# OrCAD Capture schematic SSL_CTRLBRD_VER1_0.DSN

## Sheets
1 3: MOTOR_1: size A3
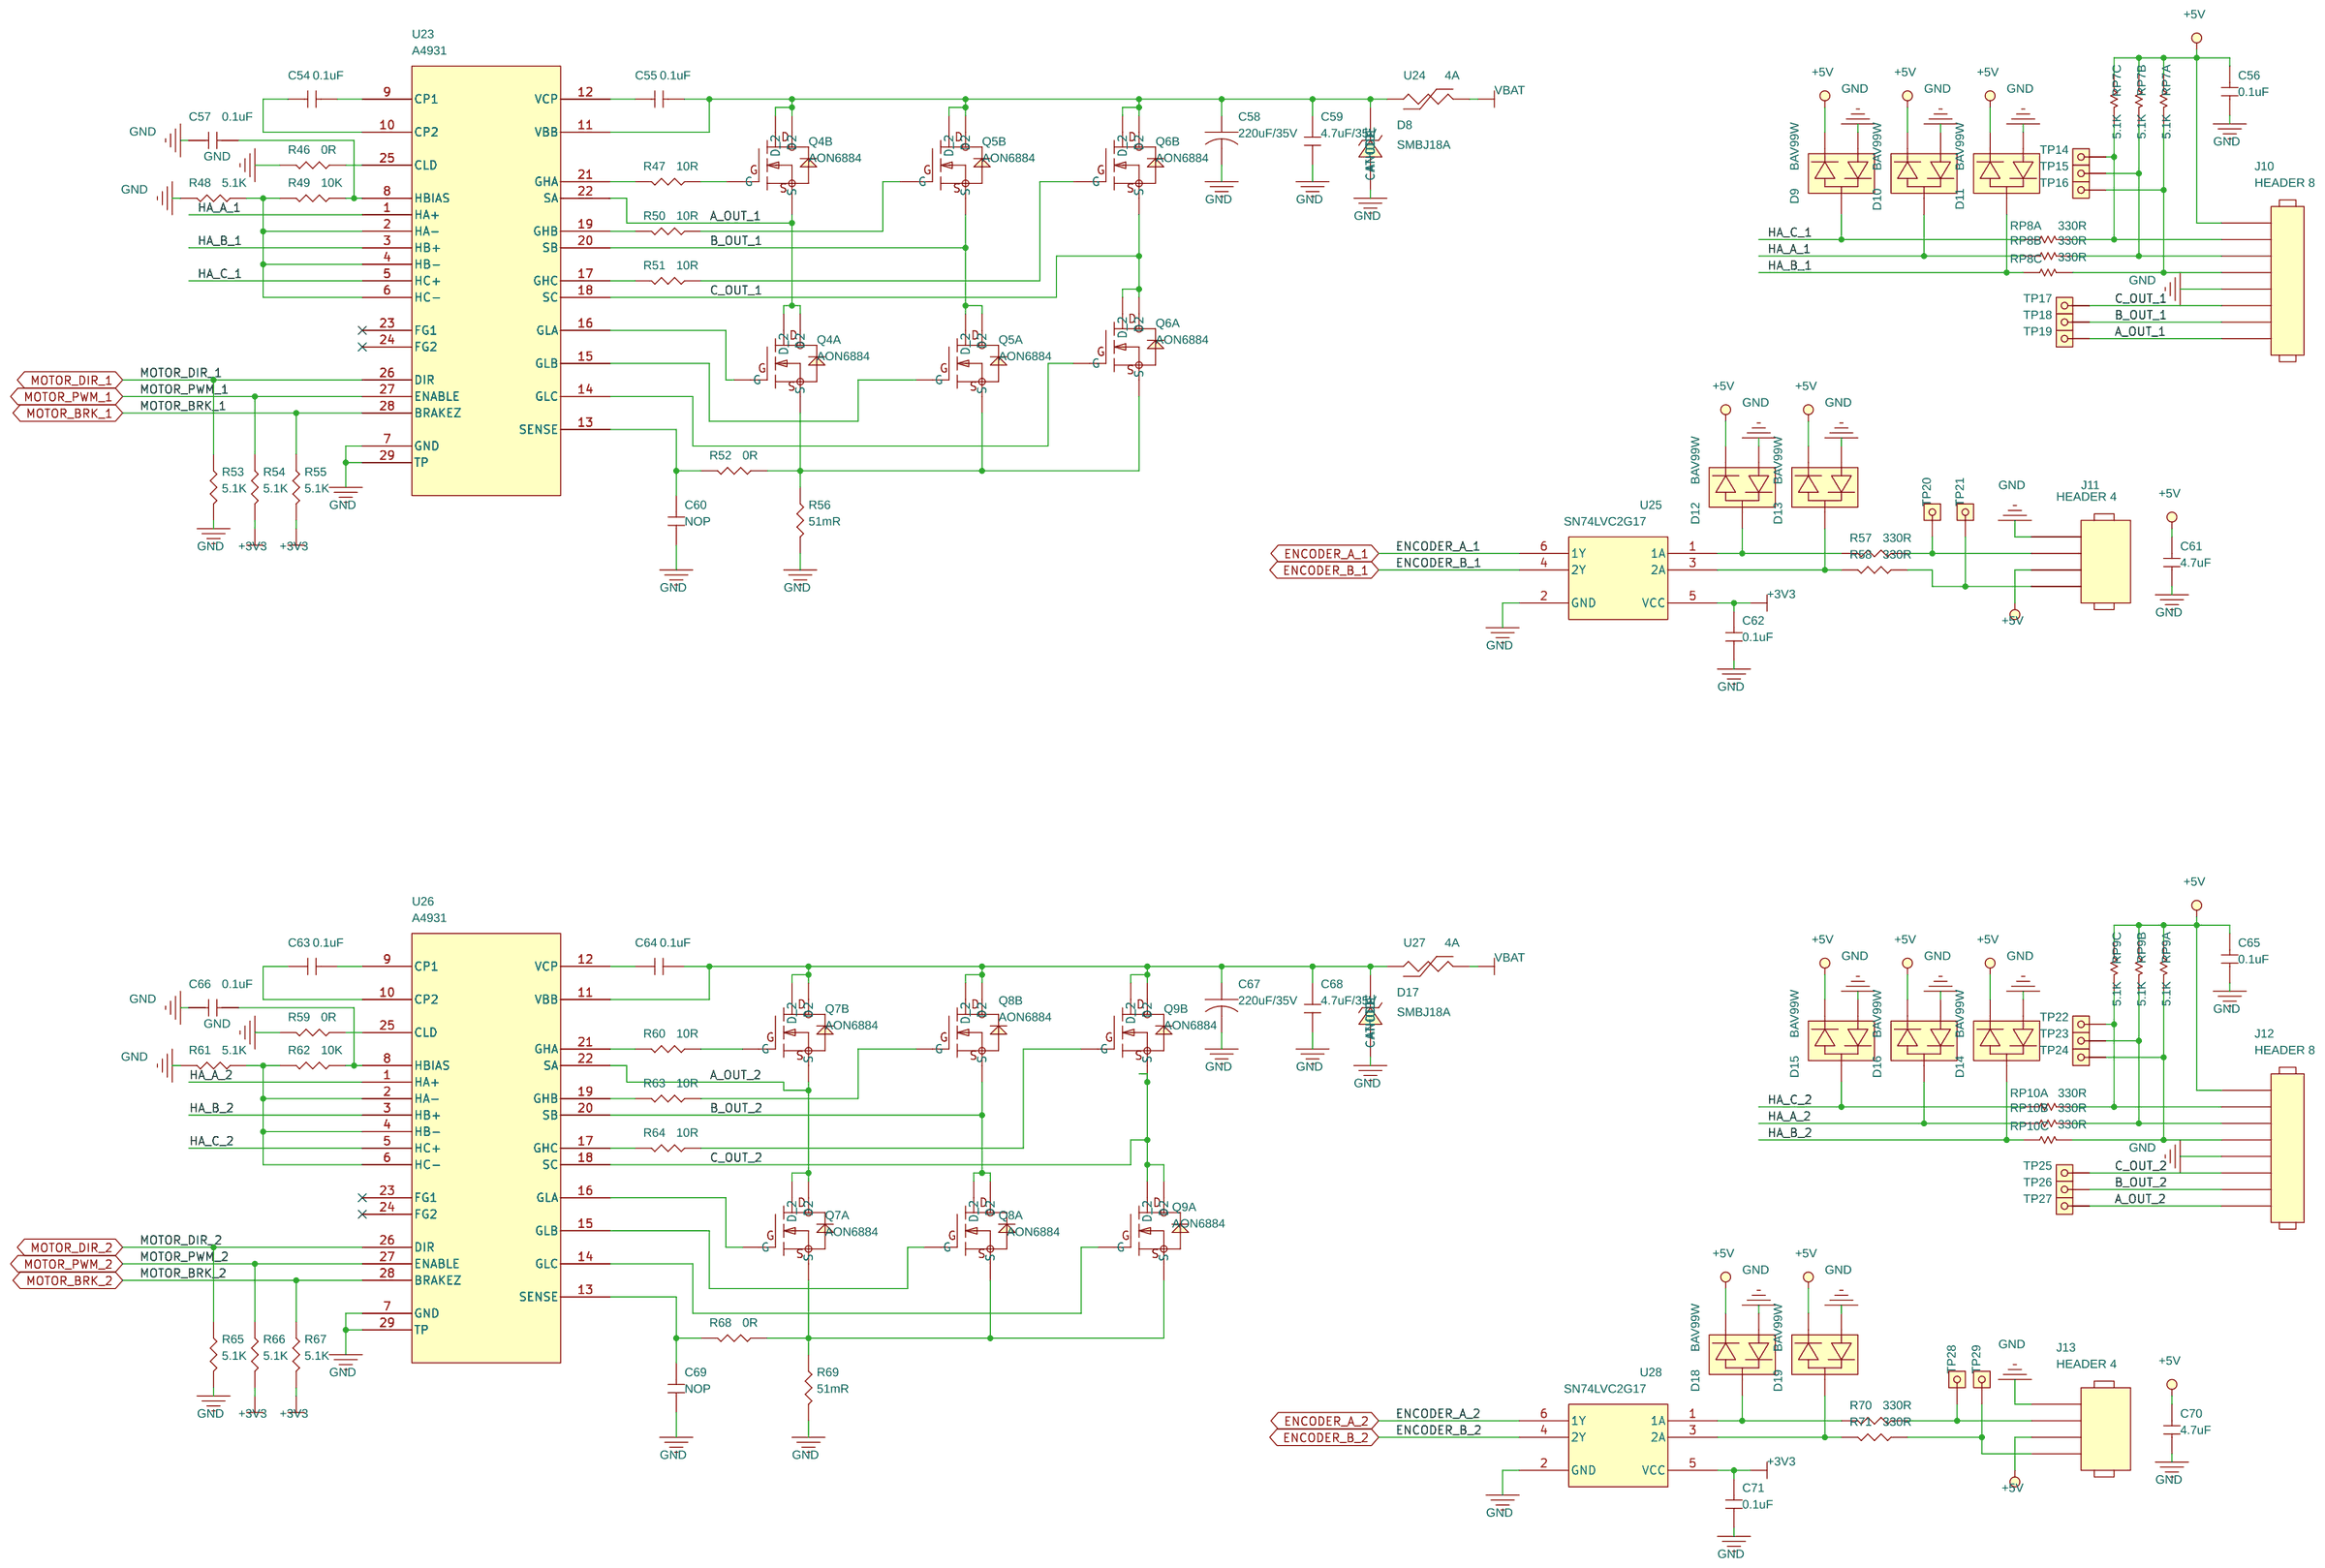
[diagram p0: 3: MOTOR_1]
2 1: MCU: size A3
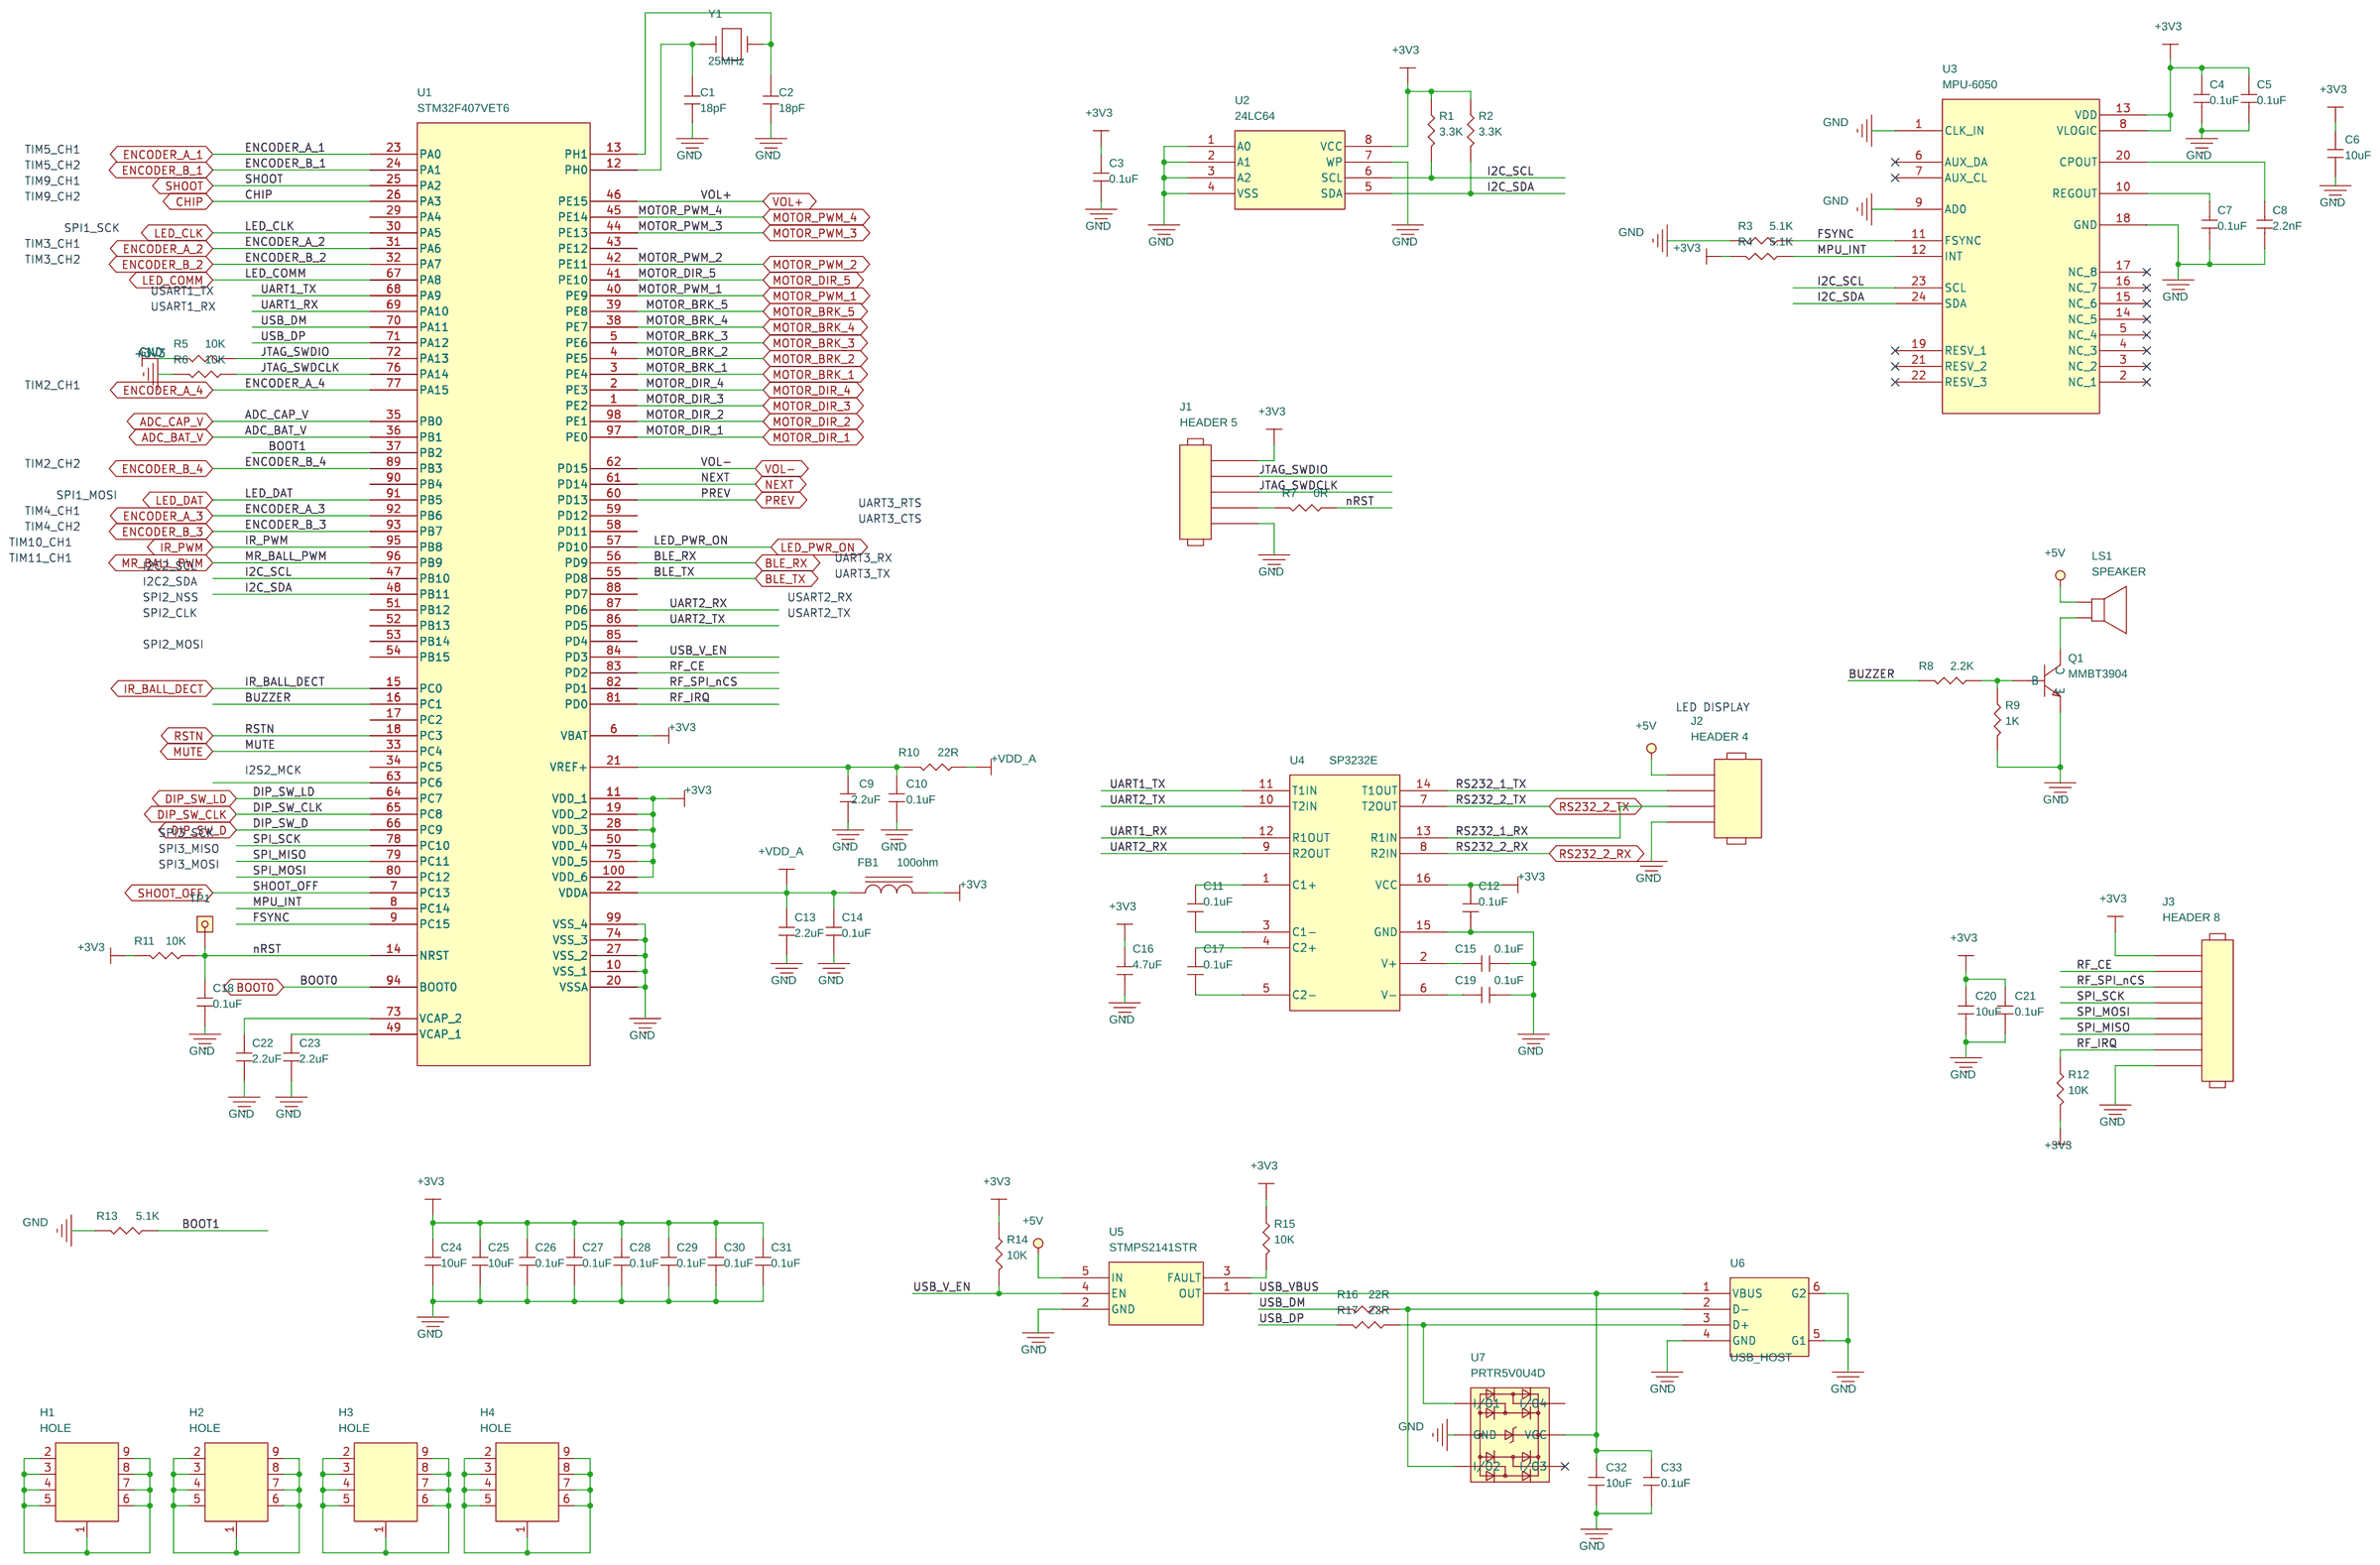
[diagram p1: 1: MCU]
3 2: IO & Power: size A3
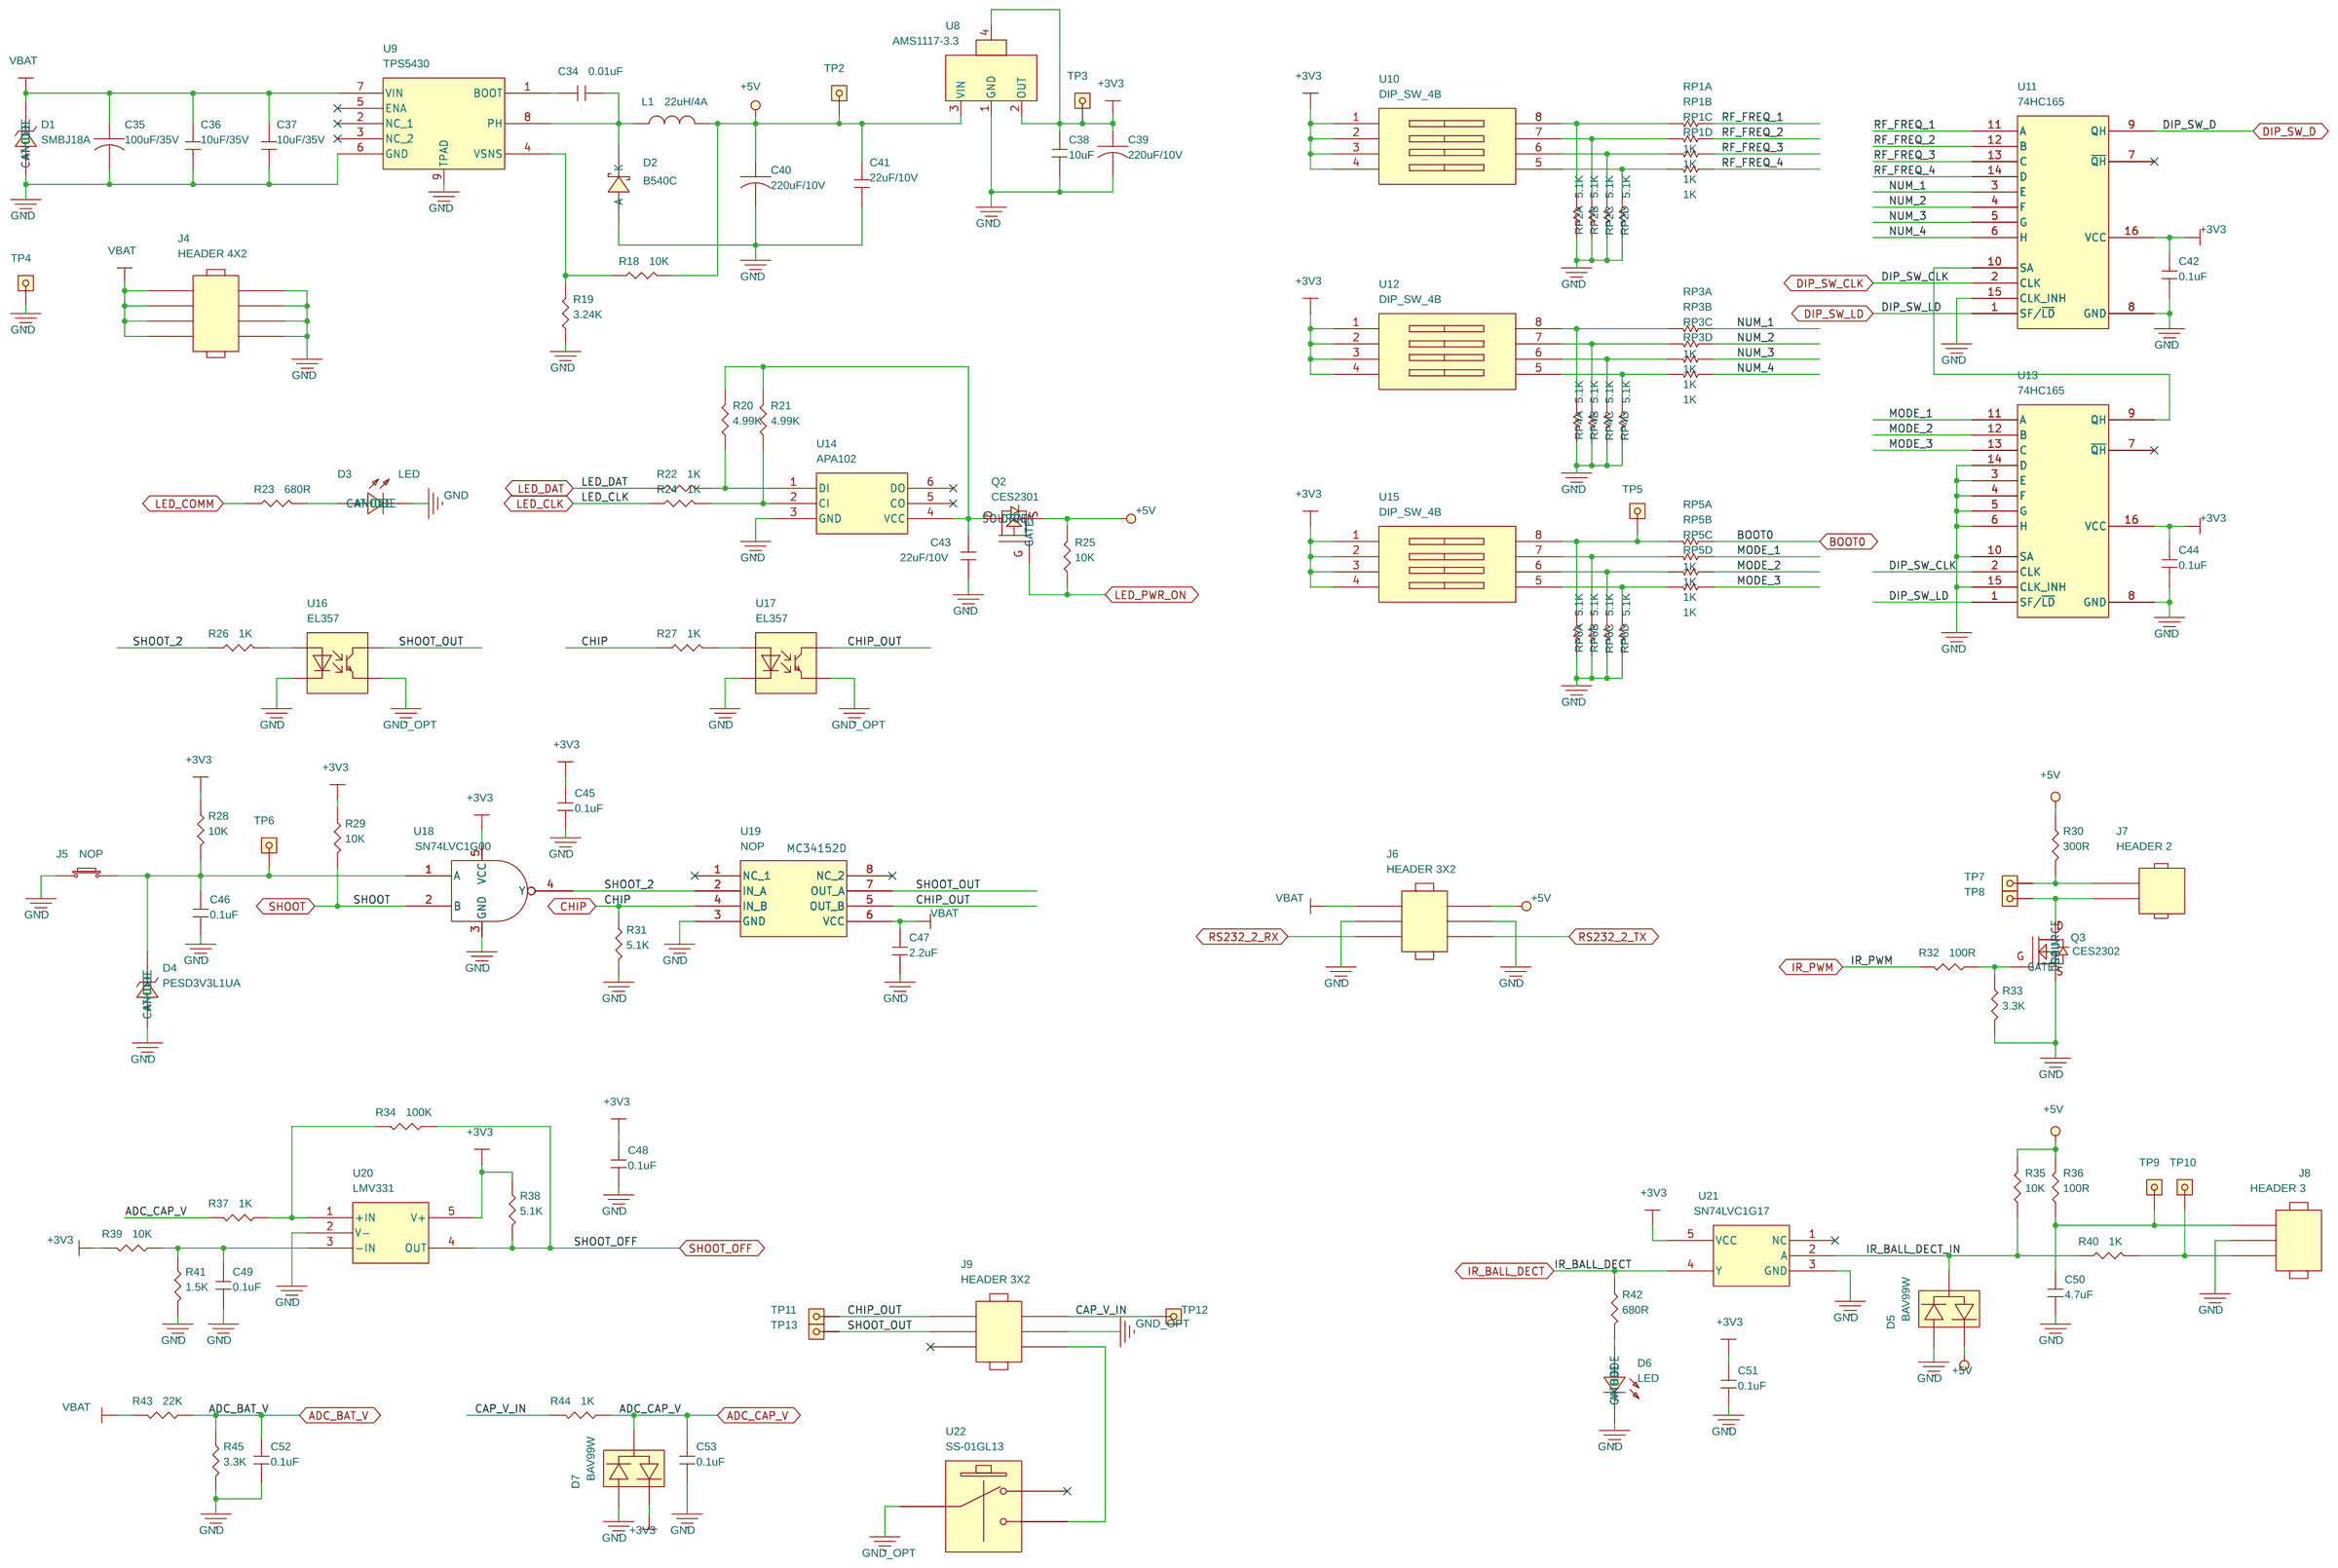
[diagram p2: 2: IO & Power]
4 4: MOTOR_2: size A3
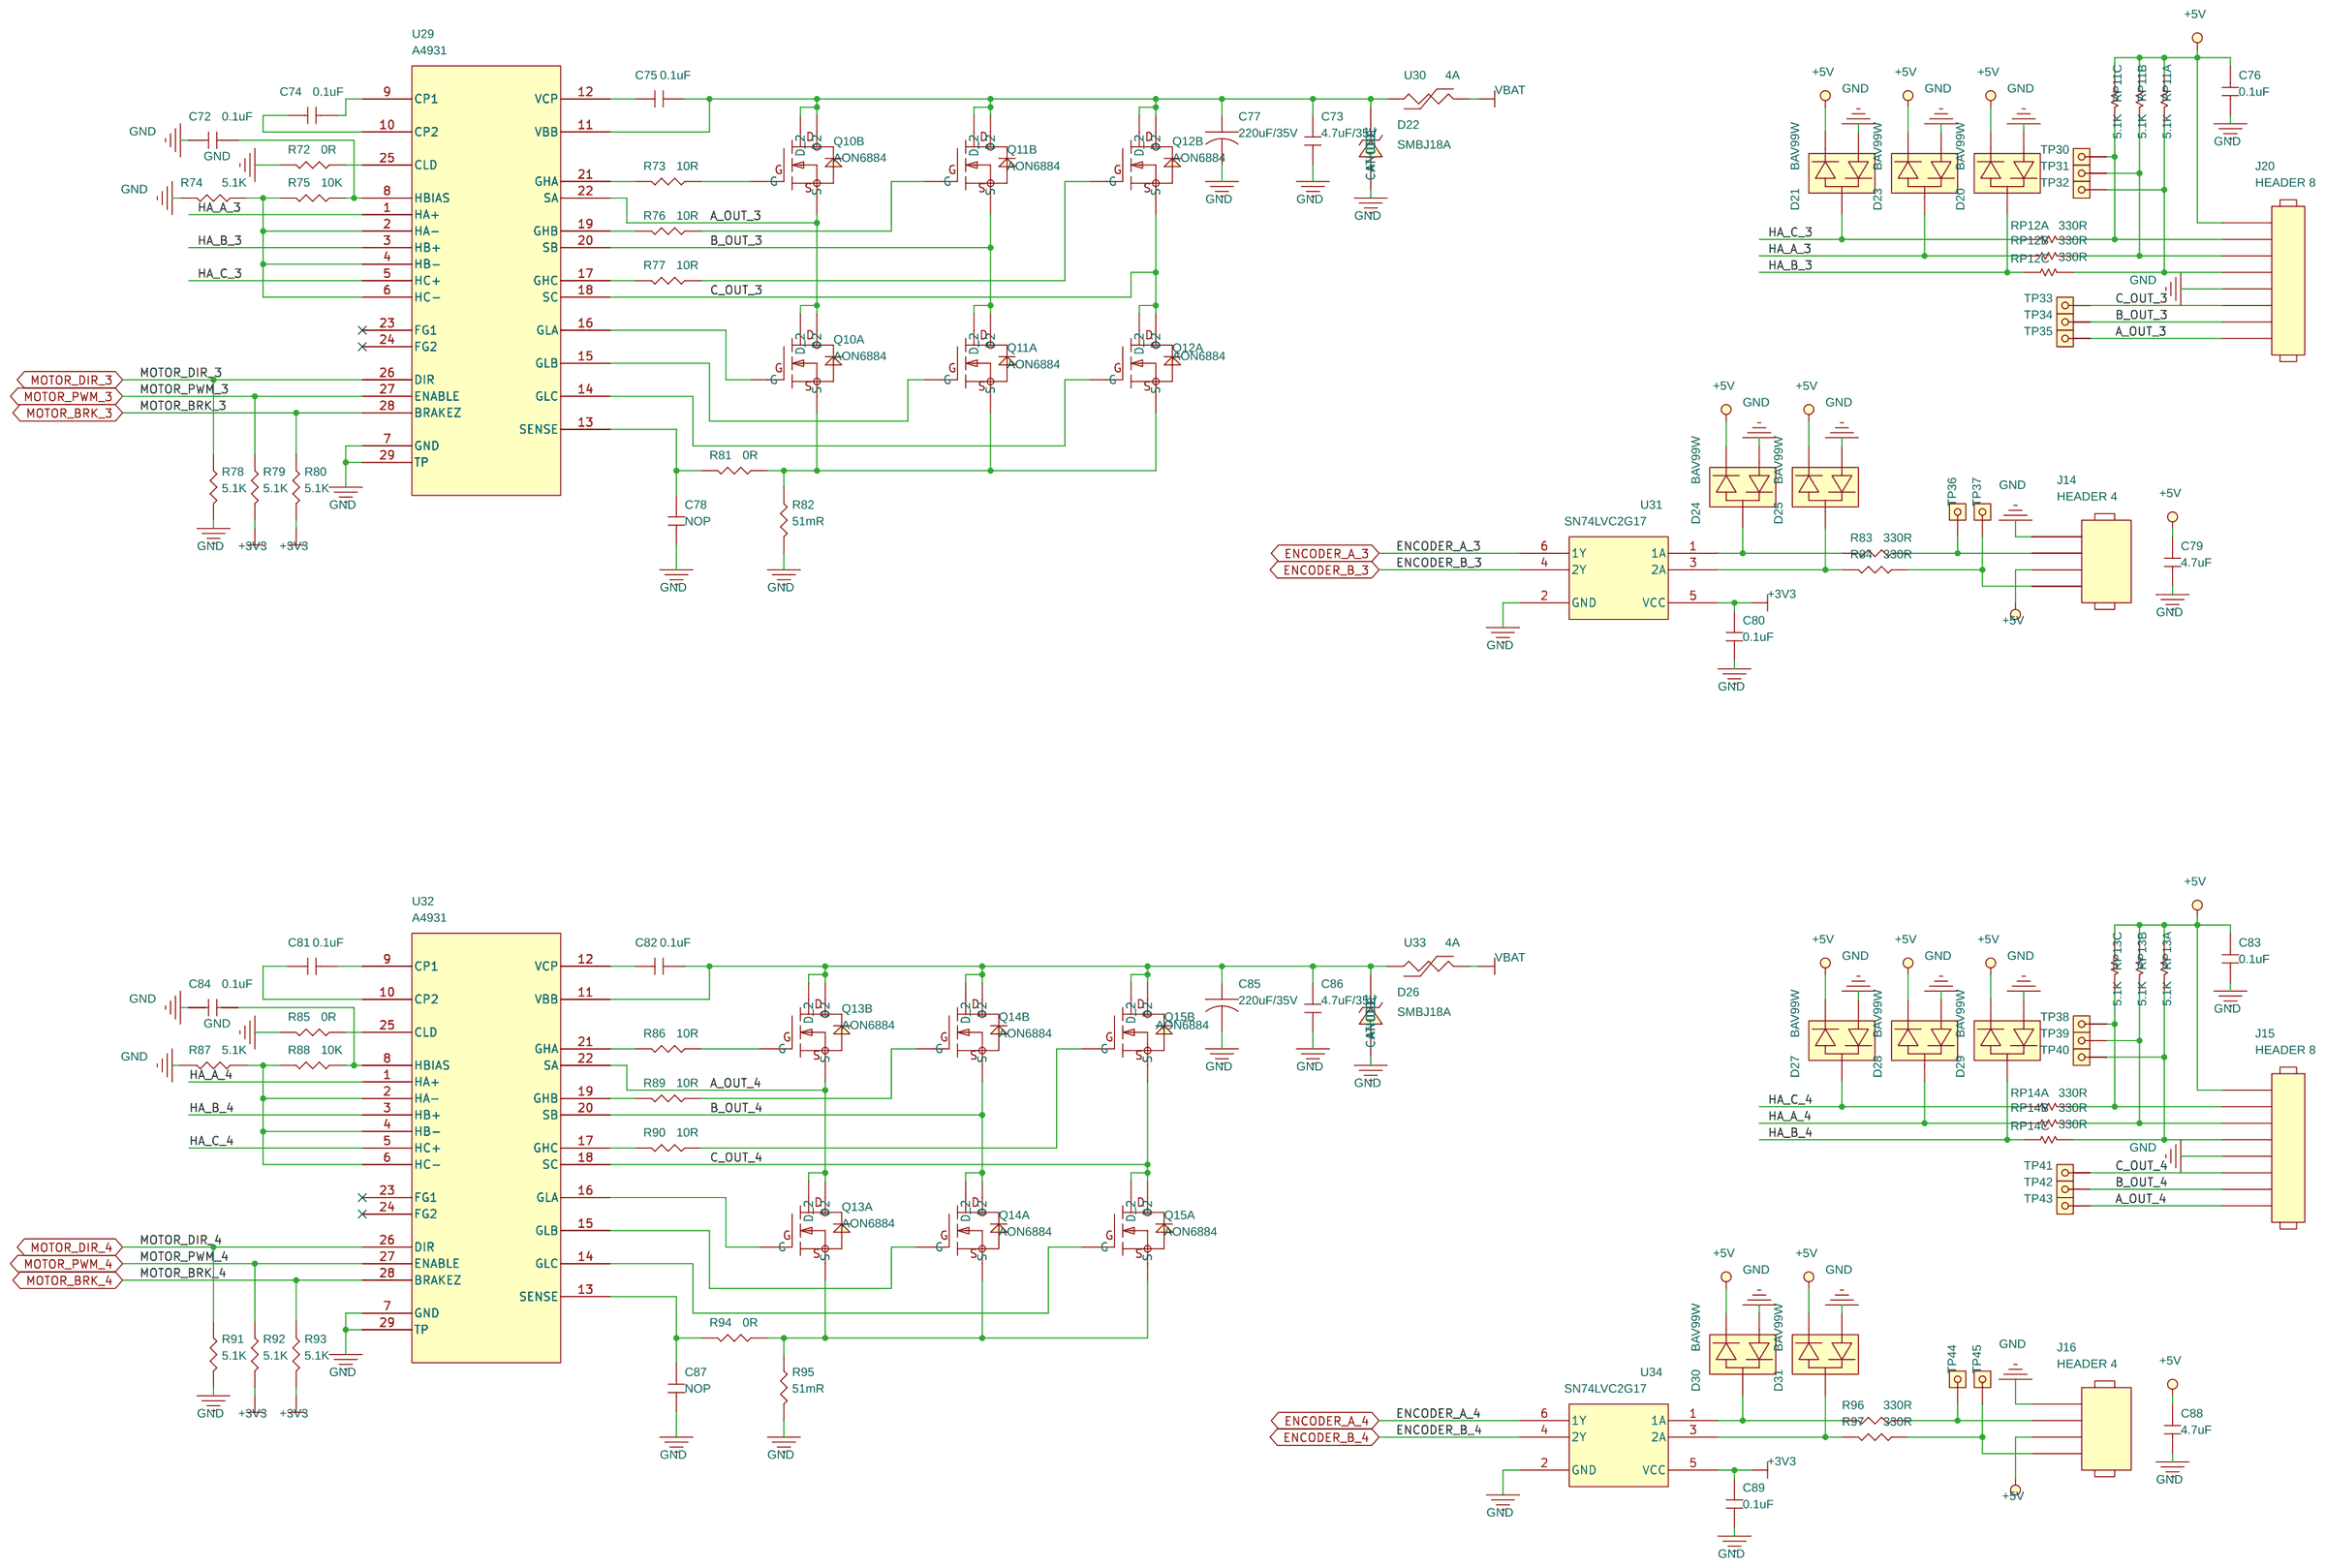
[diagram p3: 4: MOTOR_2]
5 5: MOTOR_BALL & BLE: size A3
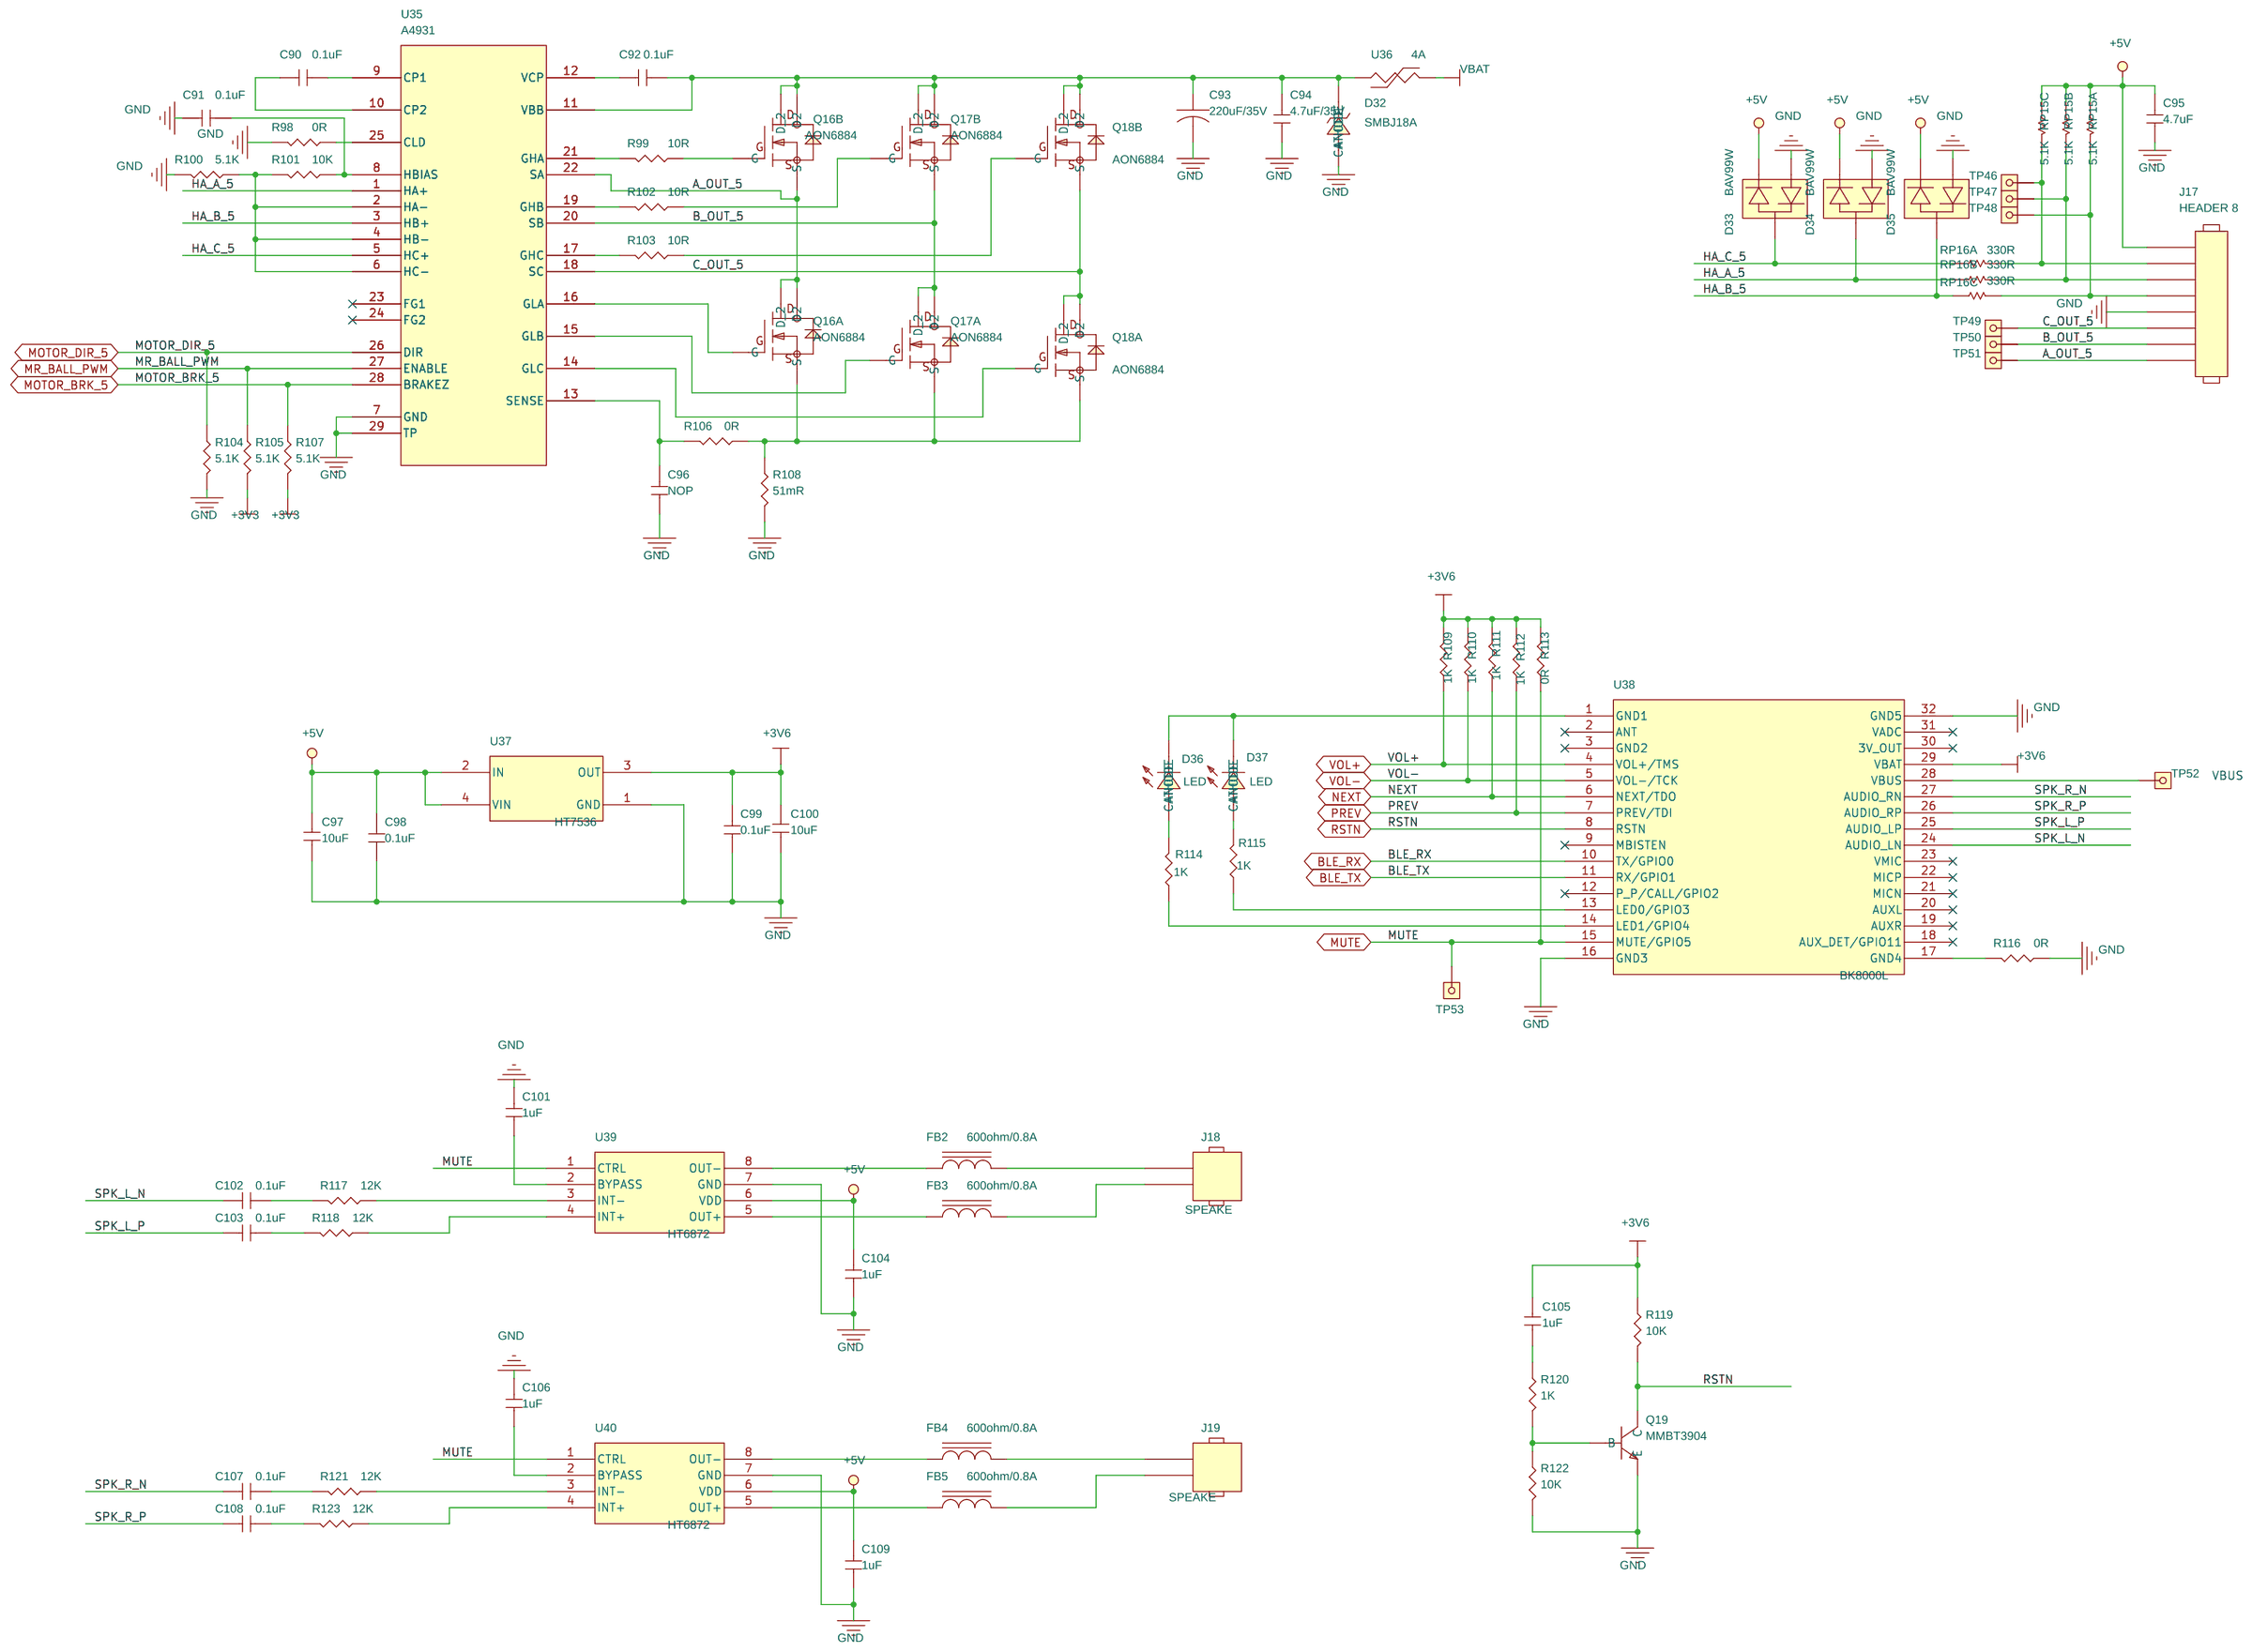
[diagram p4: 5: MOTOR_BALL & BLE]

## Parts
sheet 1: MCU
C1  18pF  [0603_C]
C2  18pF  [0603_C]
C3  0.1uF  [0603_C]
C4  0.1uF  [0603_C]
C5  0.1uF  [0603_C]
C6  10uF  [0805_C]
C7  0.1uF  [0603_C]
C8  2.2nF  [0603_C]
C9  2.2uF  [0603_C]
C10  0.1uF  [0603_C]
C11  0.1uF  [0603_C]
C12  0.1uF  [0603_C]
C13  2.2uF  [0603_C]
C14  0.1uF  [0603_C]
C15  0.1uF  [0603_C]
C16  4.7uF  [0603_C]
C17  0.1uF  [0603_C]
C18  0.1uF  [0603_C]
C19  0.1uF  [0603_C]
C20  10uF  [0805_C]
C21  0.1uF  [0603_C]
C22  2.2uF  [0603_C]
C23  2.2uF  [0603_C]
C24  10uF  [0805_C]
C25  10uF  [0805_C]
C26  0.1uF  [0603_C]
C27  0.1uF  [0603_C]
C28  0.1uF  [0603_C]
C29  0.1uF  [0603_C]
C30  0.1uF  [0603_C]
C31  0.1uF  [0603_C]
C32  10uF  [0805_C]
C33  0.1uF  [0603_C]
FB1  100ohm  [0603_L]
H1  HOLE  [HOLE_3]
H2  HOLE  [HOLE_3]
H3  HOLE  [HOLE_3]
H4  HOLE  [HOLE_3]
J1  HEADER 5  [HDR200MS-1X5]
J2  HEADER 4  [HDR200MS-2X2]
J3  HEADER 8  [E01-ML01SP2]
LS1  SPEAKER  [BEEP_500mil]
Q1  MMBT3904  [SOT23]
R1  3.3K  [0603_R]
R2  3.3K  [0603_R]
R3  5.1K  [0603_R]
R4  5.1K  [0603_R]
R5  10K  [0603_R]
R6  10K  [0603_R]
R7  0R  [0603_R]
R8  2.2K  [0603_R]
R9  1K  [0603_R]
R10  22R  [0603_R]
R11  10K  [0603_R]
R12  10K  [0603_R]
R13  5.1K  [0603_R]
R14  10K  [0603_R]
R15  10K  [0603_R]
R16  22R  [0603_R]
R17  22R  [0603_R]
TP1  TP  [TP6]
U1  STM32F407VET6  [TQFP100]
U2  24LC64  [SO-8]
U3  MPU-6050  [qfn24_157x157_197_no_ep]
U4  SP3232E  [TSSOP-16]
U5  STMPS2141STR  [SOT23-5]
U6  USB_HOST  [USB_A_SHORT]
U7  PRTR5V0U4D  [SOT23-6]
Y1  25MHz  [OSCSC254P500X320X100-2]
sheet 2: IO & Power
C34  0.01uF  [0603_C]
C35  100uF/35V  [cap_e_smd_250]
C36  10uF/35V  [1206_C]
C37  10uF/35V  [1206_C]
C38  10uF  [0805_C]
C39  220uF/10V  [cap_e_smd_250]
C40  220uF/10V  [cap_e_smd_250]
C41  22uF/10V  [0805_C]
C42  0.1uF  [0603_C]
C43  22uF/10V  [0805_C]
C44  0.1uF  [0603_C]
C45  0.1uF  [0603_C]
C46  0.1uF  [0603_C]
C47  2.2uF  [0603_C]
C48  0.1uF  [0603_C]
C49  0.1uF  [0603_C]
C50  4.7uF  [0603_C]
C51  0.1uF  [0603_C]
C52  0.1uF  [0603_C]
C53  0.1uF  [0603_C]
D1  SMBJ18A  [SMB]
D2  B540C  [SMC]
D3  LED  [0603_LED]
D4  PESD3V3L1UA  [SOD-323]
D5  BAV99W  [SC70]
D6  LED  [0603_LED]
D7  BAV99W  [SC70]
J4  HEADER 4X2  [HDR254M-2X4]
J5  NOP  [SW3]
J6  HEADER 3X2  [HDR254M-2X3]
J7  HEADER 2  [HY200-WF_1X2]
J8  HEADER 3  [HY200-WF_1X3]
J9  HEADER 3X2  [HDR254M-2X3]
L1  22uH/4A  [L_12mmX12mm]
Q2  CES2301  [SOT23]
Q3  CES2302  [SOT23]
R18  10K  [0603_R]
R19  3.24K  [0603_R]
R20  4.99K  [0603_R]
R21  4.99K  [0603_R]
R22  1K  [0603_R]
R23  680R  [0603_R]
R24  1K  [0603_R]
R25  10K  [0603_R]
R26  1K  [0603_R]
R27  1K  [0603_R]
R28  10K  [0603_R]
R29  10K  [0603_R]
R30  300R  [0603_R]
R31  5.1K  [0603_R]
R32  100R  [0603_R]
R33  3.3K  [0603_R]
R34  100K  [0603_R]
R35  10K  [0603_R]
R36  100R  [0603_R]
R37  1K  [0603_R]
R38  5.1K  [0603_R]
R39  10K  [0603_R]
R40  1K  [0603_R]
R41  1.5K  [0603_R]
R42  680R  [0603_R]
R43  22K  [0603_R]
R44  1K  [0603_R]
R45  3.3K  [0603_R]
RP1  1K  [0603_8P4R]  (sections A,B,C,D)
RP2  5.1K  [0603_8P4R]  (sections A,B,C,D)
RP3  1K  [0603_8P4R]  (sections A,B,C,D)
RP4  5.1K  [0603_8P4R]  (sections A,B,C,D)
RP5  1K  [0603_8P4R]  (sections A,B,C,D)
RP6  5.1K  [0603_8P4R]  (sections A,B,C,D)
TP2  TP  [TP6]
TP3  TP  [TP6]
TP4  TP  [TP6]
TP5  TP  [TP6]
TP6  TP  [TP6]
TP7  TP  [TP6]
TP8  TP  [TP6]
TP9  TP  [TP6]
TP10  TP  [TP6]
TP11  TP  [TP6]
TP12  TP  [TP6]
TP13  TP  [TP6]
U8  AMS1117-3.3  [SOT223]
U9  TPS5430  [SO-8-T-pad]
U10  DIP_SW_4B  [DIP_SW_2_54_4P]
U11  74HC165  [TSSOP-16]
U12  DIP_SW_4B  [DIP_SW_2_54_4P]
U13  74HC165  [TSSOP-16]
U14  APA102  [LED_5050]
U15  DIP_SW_4B  [DIP_SW_2_54_4P]
U16  EL357  [PC357]
U17  EL357  [PC357]
U18  SN74LVC1G00  [SOT23-5]
U19  NOP  [SO-8]
U20  LMV331  [SOT23-5]
U21  SN74LVC1G17  [SOT23-5]
U22  SS-01GL13  [SS-01GL13]
sheet 3: MOTOR_1
C54  0.1uF  [0603_C]
C55  0.1uF  [0603_C]
C56  0.1uF  [0603_C]
C57  0.1uF  [0603_C]
C58  220uF/35V  [cap_e_smd_315]
C59  4.7uF/35V  [0805_C]
C60  NOP  [0603_C]
C61  4.7uF  [0603_C]
C62  0.1uF  [0603_C]
C63  0.1uF  [0603_C]
C64  0.1uF  [0603_C]
C65  0.1uF  [0603_C]
C66  0.1uF  [0603_C]
C67  220uF/35V  [cap_e_smd_315]
C68  4.7uF/35V  [0805_C]
C69  NOP  [0603_C]
C70  4.7uF  [0603_C]
C71  0.1uF  [0603_C]
D8  SMBJ18A  [SMB]
D9  BAV99W  [SC70]
D10  BAV99W  [SC70]
D11  BAV99W  [SC70]
D12  BAV99W  [SC70]
D13  BAV99W  [SC70]
D14  BAV99W  [SC70]
D15  BAV99W  [SC70]
D16  BAV99W  [SC70]
D17  SMBJ18A  [SMB]
D18  BAV99W  [SC70]
D19  BAV99W  [SC70]
J10  HEADER 8  [HA250-AW-1X8]
J11  HEADER 4  [HY200-WF_1X4]
J12  HEADER 8  [HA250-AW-1X8]
J13  HEADER 4  [HY200-WF_1X4]
Q4  AON6884  [pwrpak_so8_dual]  (sections A,B)
Q5  AON6884  [pwrpak_so8_dual]  (sections A,B)
Q6  AON6884  [pwrpak_so8_dual]  (sections A,B)
Q7  AON6884  [pwrpak_so8_dual]  (sections A,B)
Q8  AON6884  [pwrpak_so8_dual]  (sections A,B)
Q9  AON6884  [pwrpak_so8_dual]  (sections A,B)
R46  0R  [0603_R]
R47  10R  [0603_R]
R48  5.1K  [0603_R]
R49  10K  [0603_R]
R50  10R  [0603_R]
R51  10R  [0603_R]
R52  0R  [0603_R]
R53  5.1K  [0603_R]
R54  5.1K  [0603_R]
R55  5.1K  [0603_R]
R56  51mR  [0805_R]
R57  330R  [0603_R]
R58  330R  [0603_R]
R59  0R  [0603_R]
R60  10R  [0603_R]
R61  5.1K  [0603_R]
R62  10K  [0603_R]
R63  10R  [0603_R]
R64  10R  [0603_R]
R65  5.1K  [0603_R]
R66  5.1K  [0603_R]
R67  5.1K  [0603_R]
R68  0R  [0603_R]
R69  51mR  [0805_R]
R70  330R  [0603_R]
R71  330R  [0603_R]
RP7  5.1K  [0603_8P4R]  (sections A,B,C)
RP8  330R  [0603_8P4R]  (sections A,B,C)
RP9  5.1K  [0603_8P4R]  (sections A,B,C)
RP10  330R  [0603_8P4R]  (sections A,B,C)
TP14  TP  [TP6]
TP15  TP  [TP6]
TP16  TP  [TP6]
TP17  TP  [TP6]
TP18  TP  [TP6]
TP19  TP  [TP6]
TP20  TP  [TP6]
TP21  TP  [TP6]
TP22  TP  [TP6]
TP23  TP  [TP6]
TP24  TP  [TP6]
TP25  TP  [TP6]
TP26  TP  [TP6]
TP27  TP  [TP6]
TP28  TP  [TP6]
TP29  TP  [TP6]
U23  A4931  [qfn28_197x197_197_ep]
U24  4A  [1206_F]
U25  SN74LVC2G17  [SOT23-6]
U26  A4931  [qfn28_197x197_197_ep]
U27  4A  [1206_F]
U28  SN74LVC2G17  [SOT23-6]
sheet 4: MOTOR_2
C72  0.1uF  [0603_C]
C73  4.7uF/35V  [0805_C]
C74  0.1uF  [0603_C]
C75  0.1uF  [0603_C]
C76  0.1uF  [0603_C]
C77  220uF/35V  [cap_e_smd_315]
C78  NOP  [0603_C]
C79  4.7uF  [0603_C]
C80  0.1uF  [0603_C]
C81  0.1uF  [0603_C]
C82  0.1uF  [0603_C]
C83  0.1uF  [0603_C]
C84  0.1uF  [0603_C]
C85  220uF/35V  [cap_e_smd_315]
C86  4.7uF/35V  [0805_C]
C87  NOP  [0603_C]
C88  4.7uF  [0603_C]
C89  0.1uF  [0603_C]
D20  BAV99W  [SC70]
D21  BAV99W  [SC70]
D22  SMBJ18A  [SMB]
D23  BAV99W  [SC70]
D24  BAV99W  [SC70]
D25  BAV99W  [SC70]
D26  SMBJ18A  [SMB]
D27  BAV99W  [SC70]
D28  BAV99W  [SC70]
D29  BAV99W  [SC70]
D30  BAV99W  [SC70]
D31  BAV99W  [SC70]
J14  HEADER 4  [HY200-WF_1X4]
J15  HEADER 8  [HA250-AW-1X8]
J16  HEADER 4  [HY200-WF_1X4]
J20  HEADER 8  [HA250-AW-1X8]
Q10  AON6884  [pwrpak_so8_dual]  (sections A,B)
Q11  AON6884  [pwrpak_so8_dual]  (sections A,B)
Q12  AON6884  [pwrpak_so8_dual]  (sections A,B)
Q13  AON6884  [pwrpak_so8_dual]  (sections A,B)
Q14  AON6884  [pwrpak_so8_dual]  (sections A,B)
Q15  AON6884  [pwrpak_so8_dual]  (sections A,B)
R72  0R  [0603_R]
R73  10R  [0603_R]
R74  5.1K  [0603_R]
R75  10K  [0603_R]
R76  10R  [0603_R]
R77  10R  [0603_R]
R78  5.1K  [0603_R]
R79  5.1K  [0603_R]
R80  5.1K  [0603_R]
R81  0R  [0603_R]
R82  51mR  [0805_R]
R83  330R  [0603_R]
R84  330R  [0603_R]
R85  0R  [0603_R]
R86  10R  [0603_R]
R87  5.1K  [0603_R]
R88  10K  [0603_R]
R89  10R  [0603_R]
R90  10R  [0603_R]
R91  5.1K  [0603_R]
R92  5.1K  [0603_R]
R93  5.1K  [0603_R]
R94  0R  [0603_R]
R95  51mR  [0805_R]
R96  330R  [0603_R]
R97  330R  [0603_R]
RP11  5.1K  [0603_8P4R]  (sections A,B,C)
RP12  330R  [0603_8P4R]  (sections A,B,C)
RP13  5.1K  [0603_8P4R]  (sections A,B,C)
RP14  330R  [0603_8P4R]  (sections A,B,C)
TP30  TP  [TP6]
TP31  TP  [TP6]
TP32  TP  [TP6]
TP33  TP  [TP6]
TP34  TP  [TP6]
TP35  TP  [TP6]
TP36  TP  [TP6]
TP37  TP  [TP6]
TP38  TP  [TP6]
TP39  TP  [TP6]
TP40  TP  [TP6]
TP41  TP  [TP6]
TP42  TP  [TP6]
TP43  TP  [TP6]
TP44  TP  [TP6]
TP45  TP  [TP6]
U29  A4931  [qfn28_197x197_197_ep]
U30  4A  [1206_F]
U31  SN74LVC2G17  [SOT23-6]
U32  A4931  [qfn28_197x197_197_ep]
U33  4A  [1206_F]
U34  SN74LVC2G17  [SOT23-6]
sheet 5: MOTOR_BALL & BLE
C90  0.1uF  [0603_C]
C91  0.1uF  [0603_C]
C92  0.1uF  [0603_C]
C93  220uF/35V  [cap_e_smd_315]
C94  4.7uF/35V  [0805_C]
C95  4.7uF  [0603_C]
C96  NOP  [0603_C]
C97  10uF  [0805_C]
C98  0.1uF  [0603_C]
C99  0.1uF  [0603_C]
C100  10uF  [0805_C]
C101  1uF  [0603_C]
C102  0.1uF  [0603_C]
C103  0.1uF  [0603_C]
C104  1uF  [0603_C]
C105  1uF  [0603_C]
C106  1uF  [0603_C]
C107  0.1uF  [0603_C]
C108  0.1uF  [0603_C]
C109  1uF  [0603_C]
D32  SMBJ18A  [SMB]
D33  BAV99W  [SC70]
D34  BAV99W  [SC70]
D35  BAV99W  [SC70]
D36  LED  [0603_LED]
D37  LED  [0603_LED]
FB2  600ohm/0.8A  [0805_L]
FB3  600ohm/0.8A  [0805_L]
FB4  600ohm/0.8A  [0805_L]
FB5  600ohm/0.8A  [0805_L]
J17  HEADER 8  [HA250-AW-1X8]
J18  SPEAKE  [HDR250MS-1X2]
J19  SPEAKE  [HDR250MS-1X2]
Q16  AON6884  [pwrpak_so8_dual]  (sections A,B)
Q17  AON6884  [pwrpak_so8_dual]  (sections A,B)
Q18  AON6884  [pwrpak_so8_dual]  (sections A,B)
Q19  MMBT3904  [SOT23]
R98  0R  [0603_R]
R99  10R  [0603_R]
R100  5.1K  [0603_R]
R101  10K  [0603_R]
R102  10R  [0603_R]
R103  10R  [0603_R]
R104  5.1K  [0603_R]
R105  5.1K  [0603_R]
R106  0R  [0603_R]
R107  5.1K  [0603_R]
R108  51mR  [0805_R]
R109  1K  [0603_R]
R110  1K  [0603_R]
R111  1K  [0603_R]
R112  1K  [0603_R]
R113  0R  [0603_R]
R114  1K  [0603_R]
R115  1K  [0603_R]
R116  0R  [0603_R]
R117  12K  [0603_R]
R118  12K  [0603_R]
R119  10K  [0603_R]
R120  1K  [0603_R]
R121  12K  [0603_R]
R122  10K  [0603_R]
R123  12K  [0603_R]
RP15  5.1K  [0603_8P4R]  (sections A,B,C)
RP16  330R  [0603_8P4R]  (sections A,B,C)
TP46  TP  [TP6]
TP47  TP  [TP6]
TP48  TP  [TP6]
TP49  TP  [TP6]
TP50  TP  [TP6]
TP51  TP  [TP6]
TP52  TP  [TP6]
TP53  TP  [TP6]
U35  A4931  [qfn28_197x197_197_ep]
U36  4A  [1206_F]
U37  HT7536  [SOT-89]
U38  BK8000L  [BK8000L]
U39  HT6872  [SO-8]
U40  HT6872  [SO-8]

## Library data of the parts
C1 C2 = CAP_NP: 瓷片电容，5%，NPO, 50V, 0603; Part Number: 通用; Vendor: 通用
C3-C5 C7 C10 C14 C18 C21 C26-C31 C33 C42 C44-C46 C48 C49 C51-C53 C62 C71 C80 C89-C92 C96 C98 C99 C101-C104 C106-C109 = CAP_NP: 瓷片电容，10%，X5R, 50V, 0603; Part Number: 通用; Vendor: 通用
C6 C20 C24 C25 C32 C38 C50 C61 C70 C79 C88 C95 C97 C100 C105 = CAP_NP: 瓷片电容，20%，X5R, 16V, 0603; Part Number: 通用; Vendor: 通用
C8 C34 = CAP_NP: 瓷片电容，10%，X7R, 50V, 0603; Part Number: 通用; Vendor: 通用
C9 C13 C22 C23 C47 = CAP_NP: 瓷片电容，20%，X5R, 25V, 0603; Part Number: 通用; Vendor: 通用
C11 C12 C15 C17 C19 = CAP_NP: Ceramic Cap., 25V, X7R, 10%; Part Number: General; Vendor: General
C16 = CAP_NP: Ceramic Cap., 10V, X5R, 20%; Part Number: General; Vendor: General
FB1 = FB: 磁珠,0603, 400mA; Part Number: 通用; Vendor: 通用
H1-H4 = HOLE: 安装孔; Part Number: 通用; Vendor: 通用
J1 = HEADER_5: 2.0mm，插座，5pin; Part Number: 通用; Vendor: 通用
J2 = HEADER_4
J3 = HEADER_8: NRF24L01P 模块; Vendor: 通用
LS1 = SPEAKER: 蜂鸣器，5V，有源，12mm; Part Number: 通用; Vendor: 通用
Q1 Q19 = NPN,SOT23: NPN; Part Number: MMBT3904LT1G; Vendor: OnSemi
R1-R45 R57 R58 R65 R70 R71 R83 R84 R96-R107 R109-R123 = RES_2: SMD通用电阻，1%，1/16W, 0603; Part Number: 通用; Vendor: 通用
TP1-TP13 TP20 TP21 TP28 TP29 TP36 TP37 TP44-TP51 = TP: 测试点; Part Number: 通用; Vendor: 通用
U1 = STM32F407VET6: ARM; Vendor: ST
U2 = 24LC64: EEPROM; Part Number: 24LC64-I/SN; Vendor: MICROCHIP
U3 = MPU-6050: Vendor: Invensense
U4 = MAX3232CSE: RS232; Part Number: SP3232EEY-L; Vendor: EXAR
U5 = STMPS2141STR: Vendor: ST
U6 = USB_HOST
U7 = AZC099-04S: TVS; Part Number: PRTR5V0U4Y; Vendor: NXP
Y1 = XTAL: 5032, 2pin, 无源晶振; Part Number: 通用; Vendor: 通用
C35 = CAP_P: 电解电容, 35V, 100uF, SMD, 6.3mm; Part Number: 通用; Vendor: NICHICON
C36 C37 = CAP_NP: 瓷片电容，20%，X5R, 35V, 1206; Part Number: 通用; Vendor: 通用
C39 C40 = CAP_P: 电解电容, 10V, 220uF, SMD, 6.3mm; Part Number: 通用; Vendor: NICHICON
C41 C43 = CAP_NP: 瓷片电容，20%，X5R, 10V, 0603; Part Number: 通用; Vendor: 通用
D1 D32 = ZENER: TVS; Vendor: 通用
D2 = DIODE_Schottky: 5A/40V肖特基二极管; Vendor: DIODE
D3 = LED: LED, 0603, Orange; Part Number: 通用; Vendor: 通用
D4 = ZENER: TVS; Vendor: NXP
D5 D7 D12 D13 D18 D19 D24 D25 D30 D31 D33-D35 = DIODE_2X_S_SOT23: Diode; Part Number: BAV99WT1G; Vendor: OnSemi
D6 = LED: LED, 0603, Red; Part Number: 通用; Vendor: 通用
J4 = HEADER_4X2: 2.54mm，2X3，排母; Part Number: 通用; Vendor: 通用
J5 = SW_2: 按钮; Part Number: 通用; Vendor: 通用
J6 J9 = HEADER_3X2: 2.54mm，2X3，排母; Part Number: 通用; Vendor: 通用
J7 = HEADER_2: HY2.0插座，弯针，2pin; Part Number: HY2.0; Vendor: 通用
J8 = HEADER_3: HY2.0插座，弯针，3pin; Part Number: HY2.0; Vendor: 通用
L1 = L_0: 功率电感，4A, 22uH， 12mmX12mm; Part Number: 通用; Vendor: 通用
Q2 = PMOS,SOT23
Q3 = NMOS,SOT23: MOSFET; Vendor: 长电
RP1 = RP_S: SMD通用电阻，5%，1/16W, 06; package: 1
RP2 = RP_S: SMD通用电阻，5%，1/16W, 06; package: 2
RP3 = RP_S: SMD通用电阻，5%，1/16W, 06; package: 3
RP4 = RP_S: SMD通用电阻，5%，1/16W, 06; package: 4
RP5 = RP_S: SMD通用电阻，5%，1/16W, 06; package: 5
RP6 = RP_S: SMD通用电阻，5%，1/16W, 06; package: 6
U8 = AMS1117-5.0: Power IC; Vendor: AMS
U9 = TPS5450: DC/DC; Part Number: TPS5430DDA; Vendor: TI
U10 U12 U15 = DIP_SW_4B: 贴片拨码开关， 2.54mm， 4位; Part Number: 通用; Vendor: 通用
U11 U13 = 74HC165: Logic IC; Part Number: 74HC165PW; Vendor: NXP
U14 = APA102: RGB LED， 5050; Vendor: 通用
U16 U17 = PC357: 光耦; Part Number: EL357N; Vendor: 亿光
U18 = SN74AHC1G00: Logic IC; Part Number: SN74LVC1G00DBVR; Vendor: TI
U19 = MC34152D: Vendor: OnSemi
U20 = LMV331: Part Number: LMV331IDBVR; Vendor: TI
U21 = SN74LVC1G17: Logic IC; Part Number: SN74LVC1G17DBVR; Vendor: TI
U22 = SW_7: 微动开关; Vendor: 欧姆龙
C54-C57 C60 = CAP_NP: 瓷片电容，10%，X5R, 50V, 0603; Part Number: 通用; ROOM: M1; Vendor: 通用
C58 = CAP_P: 电解电容,35V, 220uF, SMD, 8mm; Part Number: 通用; ROOM: M1; Vendor: NICHICON
C59 = CAP_NP: 瓷片电容，20%，X5R, 35V, 0805; Part Number: 通用; ROOM: M1; Vendor: 通用
C63-C66 C69 = CAP_NP: 瓷片电容，10%，X5R, 50V, 0603; Part Number: 通用; ROOM: M2; Vendor: 通用
C67 = CAP_P: 电解电容,35V, 220uF, SMD, 8mm; Part Number: 通用; ROOM: M2; Vendor: NICHICON
C68 = CAP_NP: 瓷片电容，20%，X5R, 35V, 0805; Part Number: 通用; ROOM: M2; Vendor: 通用
D8 = ZENER: TVS; ROOM: M1; Vendor: 通用
D9-D11 = DIODE_2X_S_SOT23: Diode; Part Number: BAV99WT1G; ROOM: M1; Vendor: OnSemi
D14-D16 = DIODE_2X_S_SOT23: Diode; Part Number: BAV99WT1G; ROOM: M2; Vendor: OnSemi
D17 = ZENER: TVS; ROOM: M2; Vendor: 通用
J10 = HEADER_8: HA2.5插座，弯针，8pin; Part Number: HA2.5; ROOM: M1; Vendor: 通用
J11 J13 J14 J16 = HEADER_4: HY2.0插座，弯针，4pin; Part Number: HY2.0; Vendor: 通用
J12 = HEADER_8: HA2.5插座，弯针，8pin; Part Number: HA2.5; ROOM: M2; Vendor: 通用
Q4 = AON6884: MOSFET
Q5 = AON6884: MOSFET; package: 2
Q6 = AON6884: MOSFET; package: 3
Q7 = AON6884: MOSFET; package: 4
Q8 = AON6884: MOSFET; package: 5
Q9 = AON6884: MOSFET; package: 6
R46-R55 = RES_2: SMD通用电阻，1%，1/16W, 0603; Part Number: 通用; ROOM: M1; Vendor: 通用
R56 = RES_2: SMD通用电阻，1%，1/10W, 0805; Part Number: 通用; ROOM: M1; Vendor: 通用
R59-R64 R66-R68 = RES_2: SMD通用电阻，1%，1/16W, 0603; Part Number: 通用; ROOM: M2; Vendor: 通用
R69 = RES_2: SMD通用电阻，1%，1/10W, 0805; Part Number: 通用; ROOM: M2; Vendor: 通用
RP7 = RP_S: SMD通用电阻，5%，1/16W, 06; package: 7
RP8 = RP_S: SMD通用电阻，5%，1/16W, 06; package: 8
RP9 = RP_S: SMD通用电阻，5%，1/16W, 06; package: 9
RP10 = RP_S: SMD通用电阻，5%，1/16W, 06; package: 10
TP14-TP19 TP52 TP53 = TP: 测试点; Part Number: 通用; ROOM: M1; Vendor: 通用
TP22-TP27 = TP: 测试点; Part Number: 通用; ROOM: M2; Vendor: 通用
U23 = A4931: Motor Driver; Part Number: A4931METTR-T; ROOM: M1; Vendor: Allegro
U24 = FUSE: 熔断丝，SMD，4A，1206; Part Number: 通用; ROOM: M1; Vendor: 通用
U25 U28 U31 U34 = SN74LVC2G17: Logic IC; Part Number: SN74LVC2G17DBVR; Vendor: TI
U26 = A4931: Motor Driver; Part Number: A4931METTR-T; ROOM: M2; Vendor: Allegro
U27 = FUSE: 熔断丝，SMD，4A，1206; Part Number: 通用; ROOM: M2; Vendor: 通用
C72 C74-C76 C78 = CAP_NP: 瓷片电容，10%，X5R, 50V, 0603; Part Number: 通用; ROOM: M3; Vendor: 通用
C73 = CAP_NP: 瓷片电容，20%，X5R, 35V, 0805; Part Number: 通用; ROOM: M3; Vendor: 通用
C77 = CAP_P: 电解电容,35V, 220uF, SMD, 8mm; Part Number: 通用; ROOM: M3; Vendor: NICHICON
C81-C84 C87 = CAP_NP: 瓷片电容，10%，X5R, 50V, 0603; Part Number: 通用; ROOM: M4; Vendor: 通用
C85 = CAP_P: 电解电容,35V, 220uF, SMD, 8mm; Part Number: 通用; ROOM: M4; Vendor: NICHICON
C86 = CAP_NP: 瓷片电容，20%，X5R, 35V, 0805; Part Number: 通用; ROOM: M4; Vendor: 通用
D20 D21 D23 = DIODE_2X_S_SOT23: Diode; Part Number: BAV99WT1G; ROOM: M3; Vendor: OnSemi
D22 = ZENER: TVS; ROOM: M3; Vendor: 通用
D26 = ZENER: TVS; ROOM: M4; Vendor: 通用
D27-D29 = DIODE_2X_S_SOT23: Diode; Part Number: BAV99WT1G; ROOM: M4; Vendor: OnSemi
J15 J20 = HEADER_8: HA2.5插座，弯针，8pin; Part Number: HA2.5; ROOM: M4; Vendor: 通用
Q10 = AON6884: MOSFET; package: 7
Q11 = AON6884: MOSFET; package: 8
Q12 = AON6884: MOSFET; package: 9
Q13 = AON6884: MOSFET; package: 11
Q14 = AON6884: MOSFET; package: 12
Q15 = AON6884: MOSFET; package: 13
R72-R81 = RES_2: SMD通用电阻，1%，1/16W, 0603; Part Number: 通用; ROOM: M3; Vendor: 通用
R82 = RES_2: SMD通用电阻，1%，1/10W, 0805; Part Number: 通用; ROOM: M3; Vendor: 通用
R85-R94 = RES_2: SMD通用电阻，1%，1/16W, 0603; Part Number: 通用; ROOM: M4; Vendor: 通用
R95 = RES_2: SMD通用电阻，1%，1/10W, 0805; Part Number: 通用; ROOM: M4; Vendor: 通用
RP11 = RP_S: SMD通用电阻，5%，1/16W, 06; package: 11
RP12 = RP_S: SMD通用电阻，5%，1/16W, 06; package: 12
RP13 = RP_S: SMD通用电阻，5%，1/16W, 06; package: 13
RP14 = RP_S: SMD通用电阻，5%，1/16W, 06; package: 14
TP30-TP35 = TP: 测试点; Part Number: 通用; ROOM: M3; Vendor: 通用
TP38-TP43 = TP: 测试点; Part Number: 通用; ROOM: M4; Vendor: 通用
U29 = A4931: Motor Driver; Part Number: A4931METTR-T; ROOM: M3; Vendor: Allegro
U30 = FUSE: 熔断丝，SMD，4A，1206; Part Number: 通用; ROOM: M3; Vendor: 通用
U32 = A4931: Motor Driver; Part Number: A4931METTR-T; ROOM: M4; Vendor: Allegro
U33 = FUSE: 熔断丝，SMD，4A，1206; Part Number: 通用; ROOM: M4; Vendor: 通用
C93 = CAP_P: 电解电容,35V, 220uF, SMD, 8mm; Part Number: 通用; Vendor: NICHICON
C94 = CAP_NP: 瓷片电容，20%，X5R, 35V, 0805; Part Number: 通用; Vendor: 通用
D36 D37 = LED: LED, 0603, Blue; Part Number: 通用; Vendor: 通用
FB2-FB5 = FB
J17 = HEADER_8: HA2.5插座，弯针，8pin; Part Number: HA2.5; Vendor: 通用
J18 J19 = HEADER_2
Q16 = AON6884: MOSFET; package: 14
Q17 = AON6884: package: 15
Q18 = AON6884: MOSFET; package: 20
R108 = RES_2: SMD通用电阻，1%，1/10W, 0805; Part Number: 通用; Vendor: 通用
RP15 = RP_S: SMD通用电阻，5%，1/16W, 06; package: 15
RP16 = RP_S: SMD通用电阻，5%，1/16W, 06; package: 16
U35 = A4931: Motor Driver; Part Number: A4931METTR-T; Vendor: Allegro
U36 = FUSE: 熔断丝，SMD，4A，1206; Part Number: 通用; Vendor: 通用
U37 = HT7536
U38 = BK8000L
U39 U40 = HT6872

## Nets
+3V3: C3.1 C4.1 C5.1 C6.1 C12.1 C16.1 C20.1 C21.1 C24.1 C25.1 C26.1 C27.1 C28.1 C29.1 C30.1 C31.1 C38.1 C39.1 C42.1 C44.1 C45.1 C48.1 C51.1 C62.2 C71.2 C80.2 C89.2 D7.2 FB1.1 J1.1 J3.1 R1.2 R2.2 R4.1 R5.1 R11.1 R12.2 R14.1 R15.1 R28.2 R29.2 R38.2 R39.1 R54.1 R55.1 R66.1 R67.1 R79.1 R80.1 R92.1 R93.1 R105.1 R107.1 TP3.1 U1.6(VBAT) U1.11(VDD_1) U1.19(VDD_2) U1.28(VDD_3) U1.50(VDD_4) U1.75(VDD_5) U1.100(VDD_6) U2.8(VCC) U3.8(VLOGIC) U3.13(VDD) U4.16(VCC) U8.2(OUT) U8.4 U10.1 U10.2 U10.3 U10.4 U11.16(VCC) U12.1 U12.2 U12.3 U12.4 U13.16(VCC) U15.1 U15.2 U15.3 U15.4 U18.5(VCC) U20.5(V+) U21.5(VCC) U25.5(VCC) U28.5(VCC) U31.5(VCC) U34.5(VCC)
+3V6: C99.2 C100.1 C105.1 R109.2 R110.2 R111.2 R112.2 R113.2 R119.2 U37.3(OUT) U38.29(VBAT)
+5V: C40.1 C41.1 C56.2 C61.2 C65.2 C70.2 C76.2 C79.2 C83.2 C88.2 C95.2 C97.1 C98.2 C104.2 C109.2 D5.2 D9.2 D10.2 D11.2 D12.2 D13.2 D14.2 D15.2 D16.2 D18.2 D19.2 D20.2 D21.2 D23.2 D24.2 D25.2 D27.2 D28.2 D29.2 D30.2 D31.2 D33.2 D34.2 D35.2 J2.1 J6.2 J10.1 J11.3 J12.1 J13.3 J14.3 J15.1 J16.3 J17.1 J20.1 L1.1 LS1.1 Q2.2(SOURCE) R18.1 R25.1 R30.2 R35.2 R36.2 RP7.1(4) RP7.2(4) RP7.3(4) RP9.1(4) RP9.2(4) RP9.3(4) RP11.1(4) RP11.2(4) RP11.3(4) RP13.1(4) RP13.2(4) RP13.3(4) RP15.1(4) RP15.2(4) RP15.3(4) TP2.1 U5.5(IN) U8.3(VIN) U37.2(IN) U37.4(VIN) U39.6(VDD) U40.6(VDD)
+VDD_A: C13.1 C14.1 FB1.2 R10.2 U1.22(VDDA)
GND: C1.1 C2.1 C3.2 C4.2 C5.2 C6.2 C7.2 C8.2 C9.2 C10.2 C12.2 C13.2 C14.2 C15.2 C16.2 C18.2 C19.2 C20.2 C21.2 C22.2 C23.2 C24.2 C25.2 C26.2 C27.2 C28.2 C29.2 C30.2 C31.2 C32.2 C33.2 C35.2 C36.2 C37.2 C38.2 C39.2 C40.2 C41.2 C42.2 C43.2 C44.2 C45.2 C46.2 C47.2 C48.2 C49.2 C50.2 C51.2 C52.2 C53.2 C56.1 C57.1 C58.2 C59.1 C60.1 C61.1 C62.1 C65.1 C66.1 C67.2 C68.1 C69.1 C70.1 C71.1 C72.1 C73.1 C76.1 C77.2 C78.1 C79.1 C80.1 C83.1 C84.1 C85.2 C86.1 C87.1 C88.1 C89.1 C91.1 C93.2 C94.1 C95.1 C96.1 C97.2 C98.1 C99.1 C100.2 C101.2 C104.1 C106.2 C109.1 D1.1(ANODE) D2.1(A) D3.2(CATHODE) D4.1(ANODE) D5.1 D6.2(CATHODE) D7.1 D8.1(ANODE) D9.1 D10.1 D11.1 D12.1 D13.1 D14.1 D15.1 D16.1 D17.1(ANODE) D18.1 D19.1 D20.1 D21.1 D22.1(ANODE) D23.1 D24.1 D25.1 D26.1(ANODE) D27.1 D28.1 D29.1 D30.1 D31.1 D32.1(ANODE) D33.1 D34.1 D35.1 J1.5 J2.4 J3.8 J4.1 J4.3 J4.5 J4.7 J5.1 J6.3 J6.4 J8.2 J10.5 J11.1 J12.5 J13.1 J14.1 J15.5 J16.1 J17.5 J20.5 Q1.2(E) Q3.2(SOURCE) Q19.2(E) R3.1 R6.1 R9.1 R13.2 R19.2 R31.1 R33.1 R41.1 R45.1 R46.1 R48.1 R53.1 R56.1 R59.1 R61.1 R65.1 R69.1 R72.1 R74.1 R78.1 R82.1 R85.1 R87.1 R91.1 R95.1 R98.1 R100.1 R104.1 R108.1 R116.2 R122.1 RP2.5 RP2.6(5) RP2.7(5) RP2.8(5) RP4.5 RP4.6(5) RP4.7(5) RP4.8(5) RP6.5 RP6.6(5) RP6.7(5) RP6.8(5) TP4.1 U1.10(VSS_1) U1.20(VSSA) U1.27(VSS_2) U1.74(VSS_3) U1.99(VSS_4) U2.1(A0) U2.2(A1) U2.3(A2) U2.4(VSS) U2.7(WP) U3.1(CLK_IN) U3.9(AD0) U3.18(GND) U4.15(GND) U5.2(GND) U6.4(GND) U6.5(G1) U6.6(G2) U7.2(GND) U8.1(GND) U9.6(GND) U9.9(TPAD) U11.8(GND) U11.15(CLK_INH) U13.3(E) U13.4(F) U13.5(G) U13.6(H) U13.8(GND) U13.10(SA) U13.14(D) U13.15(CLK_INH) U14.3(GND) U16.2 U17.2 U18.3(GND) U19.3(GND) U20.2(V-) U21.3(GND) U23.7(GND) U23.29(TP) U25.2(GND) U26.7(GND) U26.29(TP) U28.2(GND) U29.7(GND) U29.29(TP) U31.2(GND) U32.7(GND) U32.29(TP) U34.2(GND) U35.7(GND) U35.29(TP) U37.1(GND) U38.16(GND3) U38.32(GND5) U39.7(GND) U40.7(GND)
GND_OPT: J9.4 U16.3 U17.3 U22.2
VBAT: C35.1 C36.1 C37.1 C47.1 D1.2(CATHODE) J4.2 J4.4 J4.6 J4.8 J6.1 R43.1 U9.7(VIN) U19.6(VCC) U24.2 U27.2 U30.2 U33.2 U36.2
A_OUT_1: J10.8 Q4.3(S) Q4.7(D_2) Q4.8(D2) TP19.1 U23.22(SA)
A_OUT_2: J12.8 Q7.3(S) Q7.7(D_2) Q7.8(D2) TP27.1 U26.22(SA)
A_OUT_3: J20.8 Q10.3(S) Q10.7(D_2) Q10.8(D2) TP35.1 U29.22(SA)
A_OUT_4: J15.8 Q13.3(S) Q13.7(D_2) Q13.8(D2) TP43.1 U32.22(SA)
A_OUT_5: J17.8 Q16.3(S) Q16.7(D_2) Q16.8(D2) TP51.1 U35.22(SA)
ADC_BAT_V: C52.1 R43.2 R45.2 U1.36(PB1)
ADC_CAP_V: C53.1 D7.3 R37.1 R44.2 U1.35(PB0)
B_OUT_1: J10.7 Q5.3(S) Q5.7(D_2) Q5.8(D2) TP18.1 U23.20(SB)
B_OUT_2: J12.7 Q8.3(S) Q8.7(D_2) Q8.8(D2) TP26.1 U26.20(SB)
B_OUT_3: J20.7 Q11.3(S) Q11.7(D_2) Q11.8(D2) TP34.1 U29.20(SB)
B_OUT_4: J15.7 Q14.3(S) Q14.7(D_2) Q14.8(D2) TP42.1 U32.20(SB)
B_OUT_5: J17.7 Q17.3(S) Q17.7(D_2) Q17.8(D2) TP50.1 U35.20(SB)
BLE_RX: U1.56(PD9) U38.10(TX/GPIO0)
BLE_TX: U1.55(PD8) U38.11(RX/GPIO1)
BOOT0: RP5.1(4) U1.94(BOOT0)
BOOT1: R13.1 U1.37(PB2)
BUZZER: R8.1 U1.16(PC1)
C_OUT_1: J10.6 Q6.3(S) Q6.7(D_2) Q6.8(D2) TP17.1 U23.18(SC)
C_OUT_2: J12.6 Q9.3(S) Q9.7(D_2) Q9.8(D2) TP25.1 U26.18(SC)
C_OUT_3: J20.6 Q12.3(S) Q12.7(D_2) Q12.8(D2) TP33.1 U29.18(SC)
C_OUT_4: J15.6 Q15.3(S) Q15.7(D_2) Q15.8(D2) TP41.1 U32.18(SC)
C_OUT_5: J17.6 Q18.3(S) Q18.7(D_2) Q18.8(D2) TP49.1 U35.18(SC)
CAP_V_IN: J9.2 R44.1 TP12.1
CHIP: R27.2 R31.2 U1.26(PA3) U19.4(IN_B)
CHIP_OUT: J9.1 TP11.1 U17.4 U19.5(OUT_B)
DIP_SW_CLK: U1.65(PC8) U11.2(CLK) U13.2(CLK)
DIP_SW_D: U1.66(PC9) U11.9(QH)
DIP_SW_LD: U1.64(PC7) U11.1(SF/~{LD}) U13.1(SF/~{LD})
ENCODER_A_1: U1.23(PA0) U25.6(1Y)
ENCODER_A_2: U1.31(PA6) U28.6(1Y)
ENCODER_A_3: U1.92(PB6) U31.6(1Y)
ENCODER_A_4: U1.77(PA15) U34.6(1Y)
ENCODER_B_1: U1.24(PA1) U25.4(2Y)
ENCODER_B_2: U1.32(PA7) U28.4(2Y)
ENCODER_B_3: U1.93(PB7) U31.4(2Y)
ENCODER_B_4: U1.89(PB3) U34.4(2Y)
FSYNC: R3.2 U1.9(PC15) U3.11(FSYNC)
HA_A_1: D10.3 RP8.2(4) U23.1(HA+)
HA_A_2: D16.3 RP10.2(4) U26.1(HA+)
HA_A_3: D23.3 RP12.2(4) U29.1(HA+)
HA_A_4: D28.3 RP14.2(4) U32.1(HA+)
HA_A_5: D34.3 RP16.2(4) U35.1(HA+)
HA_B_1: D11.3 RP8.3(4) U23.3(HB+)
HA_B_2: D14.3 RP10.3(4) U26.3(HB+)
HA_B_3: D20.3 RP12.3(4) U29.3(HB+)
HA_B_4: D29.3 RP14.3(4) U32.3(HB+)
HA_B_5: D35.3 RP16.3(4) U35.3(HB+)
HA_C_1: D9.3 RP8.1(4) U23.5(HC+)
HA_C_2: D15.3 RP10.1(4) U26.5(HC+)
HA_C_3: D21.3 RP12.1(4) U29.5(HC+)
HA_C_4: D27.3 RP14.1(4) U32.5(HC+)
HA_C_5: D33.3 RP16.1(4) U35.5(HC+)
I2C_SCL: R1.1 U1.47(PB10) U2.6(SCL) U3.23(SCL)
I2C_SDA: R2.1 U1.48(PB11) U2.5(SDA) U3.24(SDA)
IR_BALL_DECT: R42.2 U1.15(PC0) U21.4(Y)
IR_BALL_DECT_IN: D5.3 R35.1 R40.1 U21.2(A)
IR_PWM: R32.1 U1.95(PB8)
JTAG_SWDCLK: J1.3 R6.2 U1.76(PA14)
JTAG_SWDIO: J1.2 R5.2 U1.72(PA13)
LED_CLK: R24.2 U1.30(PA5)
LED_COMM: R23.2 U1.67(PA8)
LED_DAT: R22.2 U1.91(PB5)
LED_PWR_ON: Q2.1(GATE) R25.2 U1.57(PD10)
MODE_1: RP5.2(4) U13.11(A)
MODE_2: RP5.3(4) U13.12(B)
MODE_3: RP5.4 U13.13(C)
MOTOR_BRK_1: R55.2 U1.3(PE4) U23.28(BRAKEZ)
MOTOR_BRK_2: R67.2 U1.4(PE5) U26.28(BRAKEZ)
MOTOR_BRK_3: R80.2 U1.5(PE6) U29.28(BRAKEZ)
MOTOR_BRK_4: R93.2 U1.38(PE7) U32.28(BRAKEZ)
MOTOR_BRK_5: R107.2 U1.39(PE8) U35.28(BRAKEZ)
MOTOR_DIR_1: R53.2 U1.97(PE0) U23.26(DIR)
MOTOR_DIR_2: R65.2 U1.98(PE1) U26.26(DIR)
MOTOR_DIR_3: R78.2 U1.1(PE2) U29.26(DIR)
MOTOR_DIR_4: R91.2 U1.2(PE3) U32.26(DIR)
MOTOR_DIR_5: R104.2 U1.41(PE10) U35.26(DIR)
MOTOR_PWM_1: R54.2 U1.40(PE9) U23.27(ENABLE)
MOTOR_PWM_2: R66.2 U1.42(PE11) U26.27(ENABLE)
MOTOR_PWM_3: R79.2 U1.44(PE13) U29.27(ENABLE)
MOTOR_PWM_4: R92.2 U1.45(PE14) U32.27(ENABLE)
MPU_INT: R4.2 U1.8(PC14) U3.12(INT)
MR_BALL_PWM: R105.2 U1.96(PB9) U35.27(ENABLE)
MUTE: R113.1 TP53.1 U1.33(PC4) U38.15(MUTE/GPIO5) U39.1(CTRL) U40.1(CTRL)
NEXT: R111.1 U1.61(PD14) U38.6(NEXT/TDO)
nRST: C18.1 R7.2 R11.2 TP1.1 U1.14(NRST)
NUM_1: RP3.1(4) U11.3(E)
NUM_2: RP3.2(4) U11.4(F)
NUM_3: RP3.3(4) U11.5(G)
NUM_4: RP3.4 U11.6(H)
PREV: R112.1 U1.60(PD13) U38.7(PREV/TDI)
RF_CE: J3.2 U1.83(PD2)
RF_FREQ_1: RP1.1(4) U11.11(A)
RF_FREQ_2: RP1.2(4) U11.12(B)
RF_FREQ_3: RP1.3(4) U11.13(C)
RF_FREQ_4: RP1.4 U11.14(D)
RF_IRQ: J3.7 R12.1 U1.81(PD0)
RF_SPI_nCS: J3.3 U1.82(PD1)
RS232_1_RX: J2.3 U4.13(R1IN)
RS232_1_TX: J2.2 U4.14(T1OUT)
RS232_2_RX: J6.5 U4.8(R2IN)
RS232_2_TX: J6.6 U4.7(T2OUT)
RSTN: Q19.3(C) R119.1 U1.18(PC3) U38.8(RSTN)
SHOOT: R29.1 U1.25(PA2) U18.2(B)
SHOOT_2: R26.2 U18.4(Y) U19.2(IN_A)
SHOOT_OFF: R34.2 R38.1 U1.7(PC13) U20.4(OUT)
SHOOT_OUT: J9.3 TP13.1 U16.4 U19.7(OUT_A)
SPI_MISO: J3.6 U1.79(PC11)
SPI_MOSI: J3.5 U1.80(PC12)
SPI_SCK: J3.4 U1.78(PC10)
SPK_L_N: C102.1 U38.24(AUDIO_LN)
SPK_L_P: C103.1 U38.25(AUDIO_LP)
SPK_R_N: C107.1 U38.27(AUDIO_RN)
SPK_R_P: C108.1 U38.26(AUDIO_RP)
UART1_RX: U1.69(PA10) U4.12(R1OUT)
UART1_TX: U1.68(PA9) U4.11(T1IN)
UART2_RX: U1.87(PD6) U4.9(R2OUT)
UART2_TX: U1.86(PD5) U4.10(T2IN)
USB_DM: R16.1 U1.70(PA11)
USB_DP: R17.1 U1.71(PA12)
USB_V_EN: R14.2 U1.84(PD3) U5.4(EN)
USB_VBUS: C32.1 C33.1 U5.1(OUT) U6.1(VBUS) U7.5(VCC)
VOL+: R109.1 U1.46(PE15) U38.4(VOL+/TMS)
VOL-: R110.1 U1.62(PD15) U38.5(VOL-/TCK)
N16212342: C9.1 C10.1 R10.1 U1.21(VREF+)
N16212746: R16.2 U6.2(D-) U7.3(I/O2)
N16212776: R17.2 U6.3(D+) U7.1(I/O1)
N16213098: C7.1 U3.10(REGOUT)
N16213170: C8.1 U3.20(CPOUT)
N16214174: J1.4 R7.1
N16214228: R15.2 U5.3(FAULT)
N16214444: Q1.1(B) R8.2 R9.2
N16214506: LS1.2 Q1.3(C)
N16216300: C2.2 U1.13(PH1) Y1.1
N16216320: C1.2 U1.12(PH0) Y1.2
N16216718: C23.1 U1.49(VCAP_1)
N16216722: C22.1 U1.73(VCAP_2)
N16216872: H1.1 H1.2 H1.3 H1.4 H1.5 H1.6 H1.7 H1.8 H1.9
N16216974: H2.1 H2.2 H2.3 H2.4 H2.5 H2.6 H2.7 H2.8 H2.9
N16217080: H3.1 H3.2 H3.3 H3.4 H3.5 H3.6 H3.7 H3.8 H3.9
N16217240: H4.1 H4.2 H4.3 H4.4 H4.5 H4.6 H4.7 H4.8 H4.9
N16217582: C15.1 U4.2(V+)
N16217594: C19.1 U4.6(V-)
N16217668: C17.1 U4.4(C2+)
N16217676: C11.2 U4.3(C1-)
N16217680: C11.1 U4.1(C1+)
N16217684: C17.2 U4.5(C2-)
N16222454: C46.1 D4.2(CATHODE) J5.2 R28.1 TP6.1 U18.1(A)
N16222490: RP1.8(5) RP2.1(4) U10.8
N16222522: RP1.7(5) RP2.2(4) U10.7
N16222576: RP1.6(5) RP2.3(4) U10.6
N16222640: RP1.5 RP2.4 U10.5
N16223004: R20.2 R22.1 U14.1(DI)
N16223050: J7.1 R30.1 TP7.1
N16223096: C49.1 R39.2 R41.2 U20.3(-IN)
N16223154: C34.1 D2.2(K) L1.2 U9.8(PH)
N16223166: R18.2 R19.1 U9.4(VSNS)
N16223316: J7.2 Q3.3(DRAIN) TP8.1
N16223472: C34.2 U9.1(BOOT)
N16223708: R21.2 R24.1 U14.2(CI)
N16223800: C43.1 Q2.3(DRAIN) R20.1 R21.1 U14.4(VCC)
N16223854: D6.1(ANODE) R42.1
N16223890: U11.10(SA) U13.9(QH)
N16224232: R26.1 U16.1
N16224936: J9.6 U22.3
N16225198: Q3.1(GATE) R32.2 R33.2
N16225308: C50.1 J8.1 R36.1 TP9.1
N16225518: J8.3 R40.2 TP10.1
N16225732: R27.1 U17.1
N16226050: D3.1(ANODE) R23.1
N16226124: R34.1 R37.2 U20.1(+IN)
N16231004: J10.2 RP7.6(5) RP8.8(5) TP14.1
N16231012: J10.3 RP7.7(5) RP8.7(5) TP15.1
N16231068: J10.4 RP7.8(5) RP8.6(5) TP16.1
N16231202: J12.2 RP9.6(5) RP10.8(5) TP22.1
N16231224: J12.3 RP9.7(5) RP10.7(5) TP23.1
N16231228: J12.4 RP9.8(5) RP10.6(5) TP24.1
N16231344: J13.2 R70.2 TP28.1
N16231348: D19.3 R71.1 U28.3(2A)
N16231352: J13.4 R71.2 TP29.1
N16231410: C64.2 C67.1 C68.2 D17.2(CATHODE) Q7.5(D_2) Q7.6(D2) Q8.5(D_2) Q8.6(D2) Q9.5(D_2) Q9.6(D2) U26.11(VBB) U27.1
N16231448: C66.2 R62.2 U26.8(HBIAS)
N16231582: D18.3 R70.1 U28.1(1A)
N16231708: Q5.2(G) U23.15(GLB)
N16231980: C63.2 U26.9(CP1)
N16231984: C63.1 U26.10(CP2)
N16232020: R59.2 U26.25(CLD)
N16232070: R61.2 R62.1 U26.2(HA-) U26.4(HB-) U26.6(HC-)
N16232434: C64.1 U26.12(VCP)
N16232510: Q7.4(G) R60.2
N16232530: R60.1 U26.21(GHA)
N16232652: R63.1 U26.19(GHB)
N16232660: Q8.4(G) R63.2
N16232730: J11.2 R57.2 TP20.1
N16232734: D13.3 R58.1 U25.3(2A)
N16232738: J11.4 R58.2 TP21.1
N16232790: R64.1 U26.17(GHC)
N16232794: Q9.4(G) R64.2
N16232838: Q7.2(G) U26.16(GLA)
N16232850: Q8.2(G) U26.15(GLB)
N16232866: Q9.2(G) U26.14(GLC)
N16232926: Q7.1(S) Q8.1(S) Q9.1(S) R68.2 R69.2
N16233028: C69.2 R68.1 U26.13(SENSE)
N16233226: C55.2 C58.1 C59.2 D8.2(CATHODE) Q4.5(D_2) Q4.6(D2) Q5.5(D_2) Q5.6(D2) Q6.5(D_2) Q6.6(D2) U23.11(VBB) U24.1
N16233284: C57.2 R49.2 U23.8(HBIAS)
N16233424: D12.3 R57.1 U25.1(1A)
N16233882: C54.2 U23.9(CP1)
N16233886: C54.1 U23.10(CP2)
N16233926: R46.2 U23.25(CLD)
N16233960: R48.2 R49.1 U23.2(HA-) U23.4(HB-) U23.6(HC-)
N16234200: C55.1 U23.12(VCP)
N16234296: R47.1 U23.21(GHA)
N16234430: R50.1 U23.19(GHB)
N16234438: Q5.4(G) R50.2
N16234556: R51.1 U23.17(GHC)
N16234560: Q6.4(G) R51.2
N16234618: Q4.2(G) U23.16(GLA)
N16234658: Q6.2(G) U23.14(GLC)
N16234708: Q4.1(S) Q5.1(S) Q6.1(S) R52.2 R56.2
N16234816: C60.2 R52.1 U23.13(SENSE)
N16242851: J20.2 RP11.6(5) RP12.8(5) TP30.1
N16242877: J20.4 RP11.8(5) RP12.6(5) TP32.1
N16242881: J20.3 RP11.7(5) RP12.7(5) TP31.1
N16242947: J15.2 RP13.6(5) RP14.8(5) TP38.1
N16242969: J15.3 RP13.7(5) RP14.7(5) TP39.1
N16242981: J15.4 RP13.8(5) RP14.6(5) TP40.1
N16243085: D31.3 R97.1 U34.3(2A)
N16243089: J16.2 R96.2 TP44.1
N16243107: J16.4 R97.2 TP45.1
N16243155: C82.2 C85.1 C86.2 D26.2(CATHODE) Q13.5(D_2) Q13.6(D2) Q14.5(D_2) Q14.6(D2) Q15.5(D_2) Q15.6(D2) U32.11(VBB) U33.1
N16243193: C84.2 R88.2 U32.8(HBIAS)
N16243319: D30.3 R96.1 U34.1(1A)
N16243721: C81.1 U32.10(CP2)
N16243729: C81.2 U32.9(CP1)
N16243757: R85.2 U32.25(CLD)
N16243811: R87.2 R88.1 U32.2(HA-) U32.4(HB-) U32.6(HC-)
N16244015: C82.1 U32.12(VCP)
N16244099: Q13.4(G) R86.2
N16244111: R86.1 U32.21(GHA)
N16244229: Q14.4(G) R89.2
N16244237: R89.1 U32.19(GHB)
N16244299: J14.2 R83.2 TP36.1
N16244311: J14.4 R84.2 TP37.1
N16244315: D25.3 R84.1 U31.3(2A)
N16244363: R90.1 U32.17(GHC)
N16244387: Q15.4(G) R90.2
N16244447: Q13.2(G) U32.16(GLA)
N16244471: Q14.2(G) U32.15(GLB)
N16244479: Q15.2(G) U32.14(GLC)
N16244549: Q13.1(S) Q14.1(S) Q15.1(S) R94.2 R95.2
N16244649: C87.2 R94.1 U32.13(SENSE)
N16244783: C73.2 C75.2 C77.1 D22.2(CATHODE) Q10.5(D_2) Q10.6(D2) Q11.5(D_2) Q11.6(D2) Q12.5(D_2) Q12.6(D2) U29.11(VBB) U30.1
N16244821: C72.2 R75.2 U29.8(HBIAS)
N16244917: D24.3 R83.1 U31.1(1A)
N16245297: C74.1 U29.10(CP2)
N16245309: C74.2 U29.9(CP1)
N16245341: R72.2 U29.25(CLD)
N16245371: R74.2 R75.1 U29.2(HA-) U29.4(HB-) U29.6(HC-)
N16245565: C75.1 U29.12(VCP)
N16245657: R73.1 U29.21(GHA)
N16245661: Q10.4(G) R73.2
N16245779: Q11.4(G) R76.2
N16245787: R76.1 U29.19(GHB)
N16245901: Q12.4(G) R77.2
N16245905: R77.1 U29.17(GHC)
N16245981: Q10.2(G) U29.16(GLA)
N16246009: Q11.2(G) U29.15(GLB)
N16246065: Q12.2(G) U29.14(GLC)
N16246163: Q10.1(S) Q11.1(S) Q12.1(S) R81.2 R82.2
N16246325: C78.2 R81.1 U29.13(SENSE)
N16248666: J17.2 RP15.6(5) RP16.8(5) TP46.1
N16248688: J17.3 RP15.7(5) RP16.7(5) TP47.1
N16248692: J17.4 RP15.8(5) RP16.6(5) TP48.1
N16248822: C92.2 C93.1 C94.2 D32.2(CATHODE) Q16.5(D_2) Q16.6(D2) Q17.5(D_2) Q17.6(D2) Q18.5(D_2) Q18.6(D2) U35.11(VBB) U36.1
N16248876: C91.2 R101.2 U35.8(HBIAS)
N16249066: C90.2 U35.9(CP1)
N16249070: C90.1 U35.10(CP2)
N16249094: R98.2 U35.25(CLD)
N16249128: R100.2 R101.1 U35.2(HA-) U35.4(HB-) U35.6(HC-)
N16249326: C92.1 U35.12(VCP)
N16249418: Q16.4(G) R99.2
N16249422: R99.1 U35.21(GHA)
N16249556: R102.1 U35.19(GHB)
N16249564: Q17.4(G) R102.2
N16249674: R103.1 U35.17(GHC)
N16249706: Q16.2(G) U35.16(GLA)
N16249718: Q17.2(G) U35.15(GLB)
N16249734: Q18.2(G) U35.14(GLC)
N16249780: Q16.1(S) Q17.1(S) Q18.1(S) R106.2 R108.2
N16249898: C96.2 R106.1 U35.13(SENSE)
N16251307: D36.1(ANODE) R114.2
N16252156: C102.2 R117.1
N16252160: C103.2 R118.1
N16252164: R117.2 U39.3(INT-)
N16252176: R118.2 U39.4(INT+)
N16252300: C101.1 U39.2(BYPASS)
N16254339: C107.2 R121.1
N16254359: C108.2 R123.1
N16254363: R121.2 U40.3(INT-)
N16254367: R123.2 U40.4(INT+)
N16254401: C106.1 U40.2(BYPASS)
N16258530: Q19.1(B) R120.1 R122.2
N16259236: C105.2 R120.2
N16260621: FB2.1 U39.8(OUT-)
N16260625: FB3.1 U39.5(OUT+)
N16260645: FB3.2 J18.1
N16260657: FB2.2 J18.2
N16260735: FB4.1 U40.8(OUT-)
N16260742: FB5.1 U40.5(OUT+)
N16260748: FB4.2 J19.2
N16260758: FB5.2 J19.1
N16262221: D37.1(ANODE) R115.2
N16262712: R115.1 U38.13(LED0/GPIO3)
N16262719: R114.1 U38.14(LED1/GPIO4)
N16262726: D36.2(CATHODE) D37.2(CATHODE) U38.1(GND1)
N16265844: R116.1 U38.17(GND4)
N16266482: TP52.1 U38.28(VBUS)
N16284199: RP3.8(5) RP4.1(4) U12.8
N16284203: RP3.7(5) RP4.2(4) U12.7
N16284207: RP3.6(5) RP4.3(4) U12.6
N16284215: RP3.5 RP4.4 U12.5
N16285416: RP5.8(5) RP6.1(4) TP5.1 U15.8
N16285420: RP5.7(5) RP6.2(4) U15.7
N16285424: RP5.6(5) RP6.3(4) U15.6
N16285432: RP5.5 RP6.4 U15.5
N16299810: Q4.4(G) R47.2
N16305767: Q18.4(G) R103.2

Not connected (* = marked no-connect by the designer): J9 5*; U1 17(PC2) 29(PA4) 34(PC5) 43(PE12) 51(PB12) 52(PB13) 53(PB14) 54(PB15) 58(PD11) 59(PD12) 63(PC6) 85(PD4) 88(PD7) 90(PB4); U3 2(NC_1)* 3(NC_2)* 4(NC_3)* 5(NC_4)* 6(AUX_DA)* 7(AUX_CL)* 14(NC_5)* 15(NC_6)* 16(NC_7)* 17(NC_8)* 19(RESV_1)* 21(RESV_2)* 22(RESV_3)*; U7 4(I/O3)* 6(I/O4); U9 2(NC_1)* 3(NC_2)* 5(ENA)*; U11 7(~{QH})*; U13 7(~{QH})*; U14 5(CO)* 6(DO)*; U19 1(NC)* 8(NC_2)*; U21 1(NC)*; U22 1*; U23 23(FG1)* 24(FG2)*; U26 23(FG1)* 24(FG2)*; U29 23(FG1)* 24(FG2)*; U32 23(FG1)* 24(FG2)*; U35 23(FG1)* 24(FG2)*; U38 2(ANT)* 3(GND2)* 9(MBISTEN)* 12(P_P/CALL/GPIO2)* 18(AUX_DET/GPIO11)* 19(AUXR)* 20(AUXL)* 21(MICN)* 22(MICP)* 23(VMIC)* 30(3V_OUT)* 31(VADC)*

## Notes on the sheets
sheet 2
- TIM5_CH1
- TIM5_CH2
- TIM9_CH1
- TIM9_CH2
- TIM3_CH1
- SPI1_SCK
- TIM3_CH2
- USART1_TX
- USART1_RX
- TIM2_CH1
- TIM2_CH2
- SPI1_MOSI
- UART3_RTS
- TIM4_CH1
- UART3_CTS
- TIM4_CH2
- TIM10_CH1
- TIM11_CH1
- UART3_RX
- I2C2_SCL
- UART3_TX
- I2C2_SDA
- SPI2_CLK
- SPI2_NSS
- USART2_RX
- USART2_TX
- SPI2_MOSI
- LED DISPLAY
- I2S2_MCK
- SPI3_SCK
- SPI3_MISO
- SPI3_MOSI
sheet 3
- MC34152D
sheet 5
- VBUS
